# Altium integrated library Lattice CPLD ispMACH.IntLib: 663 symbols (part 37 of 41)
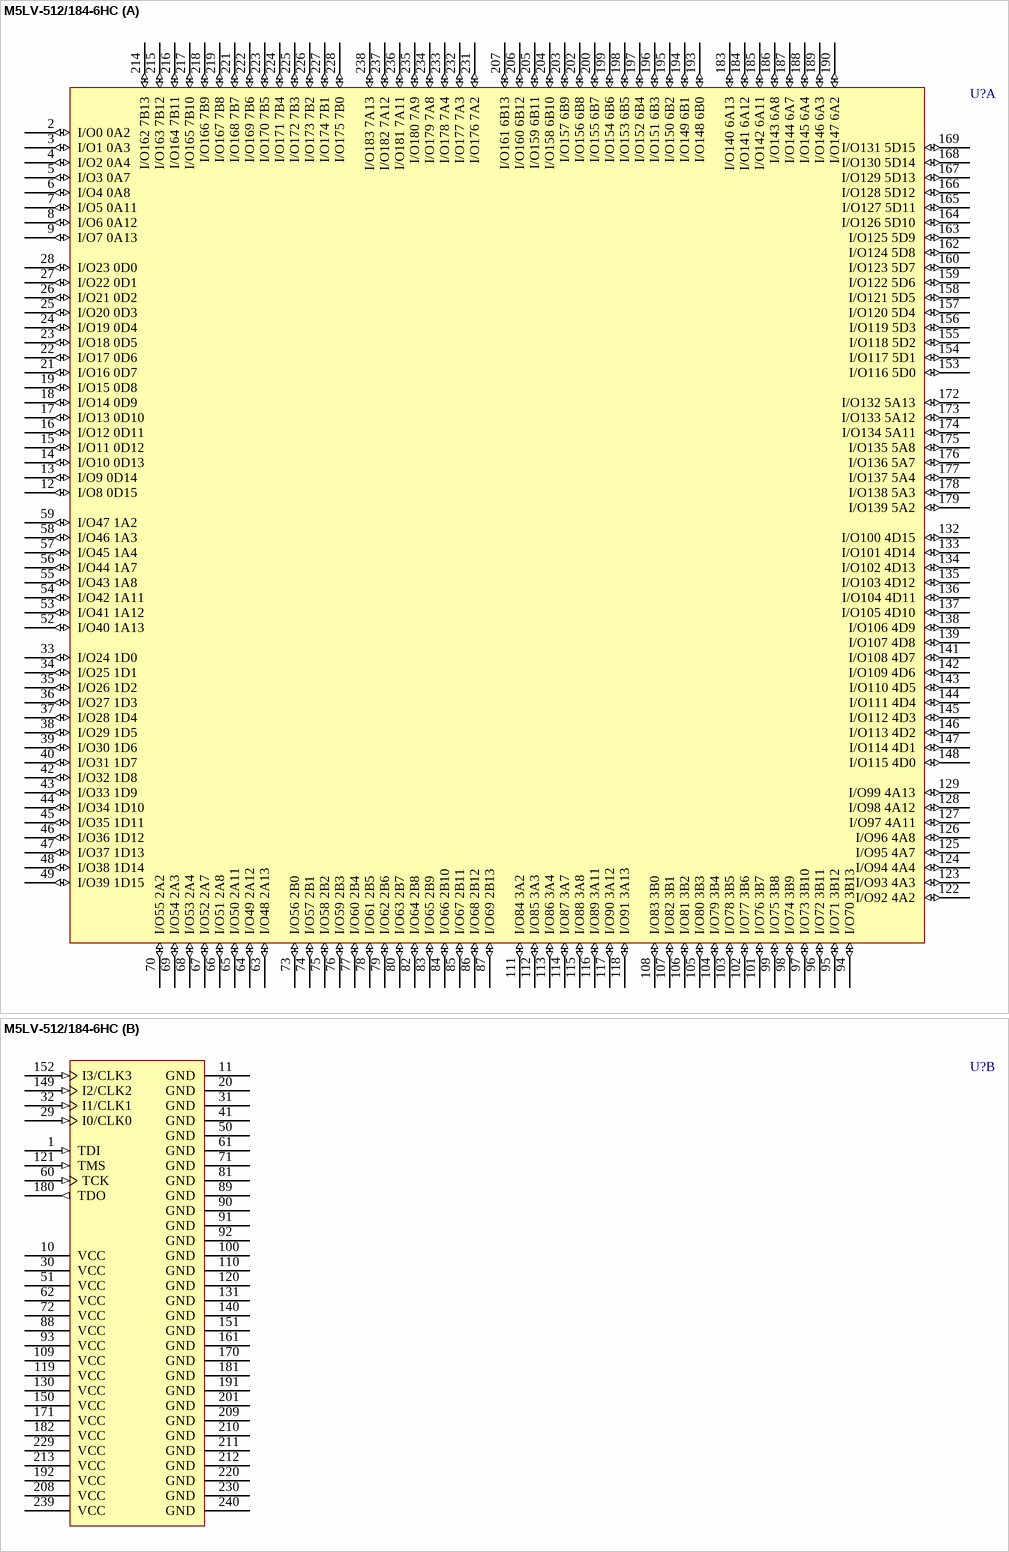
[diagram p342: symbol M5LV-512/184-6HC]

## M5LV-512/184-6HC
designator U?
High-Density and High-I/O Complex PLD
footprint PQFP240_N (Shrink QFP, 240-Leads, Body 32x32mm, Pitch 0.5mm, IPC Medium Density)
footprint PQFP240_L (Shrink QFP, 240-Leads, Body 32x32mm, Pitch 0.5mm, IPC High Density)
footprint PQFP240_M (Shrink QFP, 240-Leads, Body 32x32mm, Pitch 0.5mm, IPC Low Density)
3D model M5LV-PQFP240 (240-Pin Shrink Quad Flat Pack 0.5 mm Pitch)
part A pins: 2 I/O0 0A2 (io), 3 I/O1 0A3 (io), 4 I/O2 0A4 (io), 5 I/O3 0A7 (io), 6 I/O4 0A8 (io), 7 I/O5 0A11 (io), 8 I/O6 0A12 (io), 9 I/O7 0A13 (io), 12 I/O8 0D15 (io), 13 I/O9 0D14 (io), 14 I/O10 0D13 (io), 15 I/O11 0D12 (io), 16 I/O12 0D11 (io), 17 I/O13 0D10 (io), 18 I/O14 0D9 (io), 19 I/O15 0D8 (io), 21 I/O16 0D7 (io), 22 I/O17 0D6 (io), 23 I/O18 0D5 (io), 24 I/O19 0D4 (io), 25 I/O20 0D3 (io), 26 I/O21 0D2 (io), 27 I/O22 0D1 (io), 28 I/O23 0D0 (io), 33 I/O24 1D0 (io), 34 I/O25 1D1 (io), 35 I/O26 1D2 (io), 36 I/O27 1D3 (io), 37 I/O28 1D4 (io), 38 I/O29 1D5 (io), 39 I/O30 1D6 (io), 40 I/O31 1D7 (io), 42 I/O32 1D8 (io), 43 I/O33 1D9 (io), 44 I/O34 1D10 (io), 45 I/O35 1D11 (io), 46 I/O36 1D12 (io), 47 I/O37 1D13 (io), 48 I/O38 1D14 (io), 49 I/O39 1D15 (io), 52 I/O40 1A13 (io), 53 I/O41 1A12 (io), 54 I/O42 1A11 (io), 55 I/O43 1A8 (io), 56 I/O44 1A7 (io), 57 I/O45 1A4 (io), 58 I/O46 1A3 (io), 59 I/O47 1A2 (io), 63 I/O48 2A13 (io), 64 I/O49 2A12 (io), 65 I/O50 2A11 (io), 66 I/O51 2A8 (io), 67 I/O52 2A7 (io), 68 I/O53 2A4 (io), 69 I/O54 2A3 (io), 70 I/O55 2A2 (io), 73 I/O56 2B0 (io), 74 I/O57 2B1 (io), 75 I/O58 2B2 (io), 76 I/O59 2B3 (io), 77 I/O60 2B4 (io), 78 I/O61 2B5 (io), 79 I/O62 2B6 (io), 80 I/O63 2B7 (io), 82 I/O64 2B8 (io), 83 I/O65 2B9 (io), 84 I/O66 2B10 (io), 85 I/O67 2B11 (io), 86 I/O68 2B12 (io), 87 I/O69 2B13 (io), 94 I/O70 3B13 (io), 95 I/O71 3B12 (io), 96 I/O72 3B11 (io), 97 I/O73 3B10 (io), 98 I/O74 3B9 (io), 99 I/O75 3B8 (io), 101 I/O76 3B7 (io), 102 I/O77 3B6 (io), 103 I/O78 3B5 (io), 104 I/O79 3B4 (io), 105 I/O80 3B3 (io), 106 I/O81 3B2 (io), 107 I/O82 3B1 (io), 108 I/O83 3B0 (io), 111 I/O84 3A2 (io), 112 I/O85 3A3 (io), 113 I/O86 3A4 (io), 114 I/O87 3A7 (io), 115 I/O88 3A8 (io), 116 I/O89 3A11 (io), 117 I/O90 3A12 (io), 118 I/O91 3A13 (io), 122 I/O92 4A2 (io), 123 I/O93 4A3 (io), 124 I/O94 4A4 (io), 125 I/O95 4A7 (io), 126 I/O96 4A8 (io), 127 I/O97 4A11 (io), 128 I/O98 4A12 (io), 129 I/O99 4A13 (io), 132 I/O100 4D15 (io), 133 I/O101 4D14 (io), 134 I/O102 4D13 (io), 135 I/O103 4D12 (io), 136 I/O104 4D11 (io), 137 I/O105 4D10 (io), 138 I/O106 4D9 (io), 139 I/O107 4D8 (io), 141 I/O108 4D7 (io), 142 I/O109 4D6 (io), 143 I/O110 4D5 (io), 144 I/O111 4D4 (io), 145 I/O112 4D3 (io), 146 I/O113 4D2 (io), 147 I/O114 4D1 (io), 148 I/O115 4D0 (io), 153 I/O116 5D0 (io), 154 I/O117 5D1 (io), 155 I/O118 5D2 (io), 156 I/O119 5D3 (io), 157 I/O120 5D4 (io), 158 I/O121 5D5 (io), 159 I/O122 5D6 (io), 160 I/O123 5D7 (io), 162 I/O124 5D8 (io), 163 I/O125 5D9 (io), 164 I/O126 5D10 (io), 165 I/O127 5D11 (io), 166 I/O128 5D12 (io), 167 I/O129 5D13 (io), 168 I/O130 5D14 (io), 169 I/O131 5D15 (io), 172 I/O132 5A13 (io), 173 I/O133 5A12 (io), 174 I/O134 5A11 (io), 175 I/O135 5A8 (io), 176 I/O136 5A7 (io), 177 I/O137 5A4 (io), 178 I/O138 5A3 (io), 179 I/O139 5A2 (io), 183 I/O140 6A13 (io), 184 I/O141 6A12 (io), 185 I/O142 6A11 (io), 186 I/O143 6A8 (io), 187 I/O144 6A7 (io), 188 I/O145 6A4 (io), 189 I/O146 6A3 (io), 190 I/O147 6A2 (io), 193 I/O148 6B0 (io), 194 I/O149 6B1 (io), 195 I/O150 6B2 (io), 196 I/O151 6B3 (io), 197 I/O152 6B4 (io), 198 I/O153 6B5 (io), 199 I/O154 6B6 (io), 200 I/O155 6B7 (io), 202 I/O156 6B8 (io), 203 I/O157 6B9 (io), 204 I/O158 6B10 (io), 205 I/O159 6B11 (io), 206 I/O160 6B12 (io), 207 I/O161 6B13 (io), 214 I/O162 7B13 (io), 215 I/O163 7B12 (io), 216 I/O164 7B11 (io), 217 I/O165 7B10 (io), 218 I/O166 7B9 (io), 219 I/O167 7B8 (io), 221 I/O168 7B7 (io), 222 I/O169 7B6 (io), 223 I/O170 7B5 (io), 224 I/O171 7B4 (io), 225 I/O172 7B3 (io), 226 I/O173 7B2 (io), 227 I/O174 7B1 (io), 228 I/O175 7B0 (io), 231 I/O176 7A2 (io), 232 I/O177 7A3 (io), 233 I/O178 7A4 (io), 234 I/O179 7A8 (io), 235 I/O180 7A9 (io), 236 I/O181 7A11 (io), 237 I/O182 7A12 (io), 238 I/O183 7A13 (io)
part B pins: 1 TDI (in), 10 VCC (power), 11 GND (power), 20 GND (power), 29 I0/CLK0 (in), 30 VCC (power), 31 GND (power), 32 I1/CLK1 (in), 41 GND (power), 50 GND (power), 51 VCC (power), 60 TCK (in), 61 GND (power), 62 VCC (power), 71 GND (power), 72 VCC (power), 81 GND (power), 88 VCC (power), 89 GND (power), 90 GND (power), 91 GND (power), 92 GND (power), 93 VCC (power), 100 GND (power), 109 VCC (power), 110 GND (power), 119 VCC (power), 120 GND (power), 121 TMS (in), 130 VCC (power), 131 GND (power), 140 GND (power), 149 I2/CLK2 (in), 150 VCC (power), 151 GND (power), 152 I3/CLK3 (in), 161 GND (power), 170 GND (power), 171 VCC (power), 180 TDO (out), 181 GND (power), 182 VCC (power), 191 GND (power), 192 VCC (power), 201 GND (power), 208 VCC (power), 209 GND (power), 210 GND (power), 211 GND (power), 212 GND (power), 213 VCC (power), 220 GND (power), 229 VCC (power), 230 GND (power), 239 VCC (power), 240 GND (power)

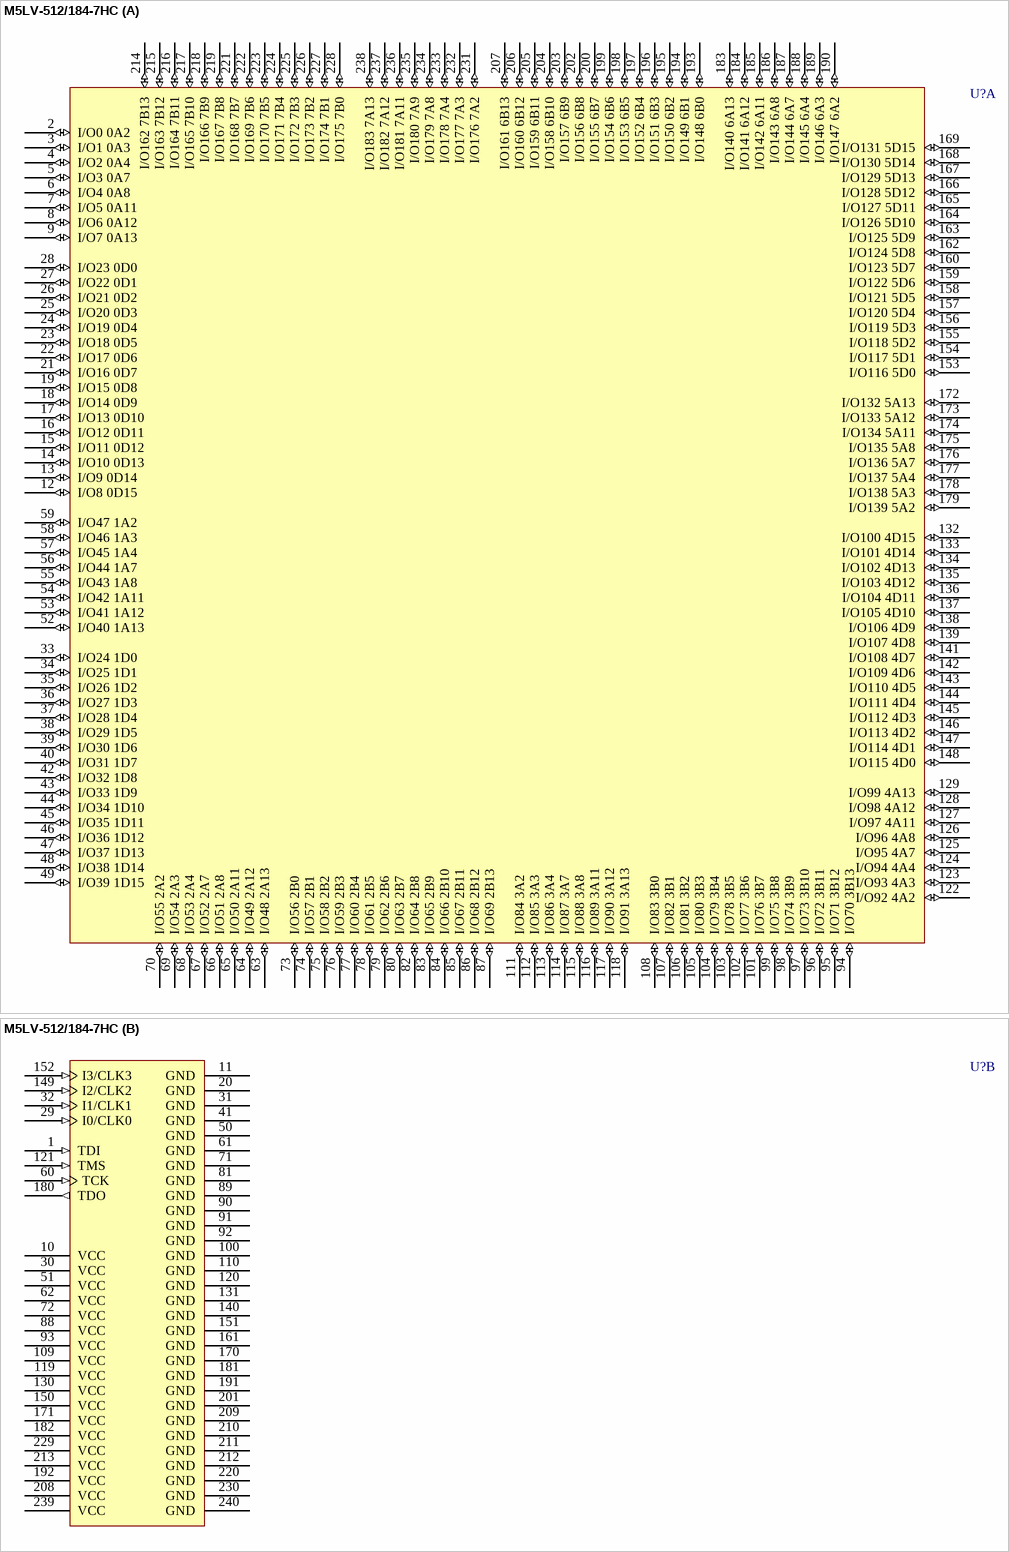
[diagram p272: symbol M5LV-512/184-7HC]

## M5LV-512/184-7HC
designator U?
High-Density and High-I/O Complex PLD
footprint PQFP240_N (Shrink QFP, 240-Leads, Body 32x32mm, Pitch 0.5mm, IPC Medium Density)
footprint PQFP240_L (Shrink QFP, 240-Leads, Body 32x32mm, Pitch 0.5mm, IPC High Density)
footprint PQFP240_M (Shrink QFP, 240-Leads, Body 32x32mm, Pitch 0.5mm, IPC Low Density)
3D model M5LV-PQFP240 (240-Pin Shrink Quad Flat Pack 0.5 mm Pitch)
part A pins: 2 I/O0 0A2 (io), 3 I/O1 0A3 (io), 4 I/O2 0A4 (io), 5 I/O3 0A7 (io), 6 I/O4 0A8 (io), 7 I/O5 0A11 (io), 8 I/O6 0A12 (io), 9 I/O7 0A13 (io), 12 I/O8 0D15 (io), 13 I/O9 0D14 (io), 14 I/O10 0D13 (io), 15 I/O11 0D12 (io), 16 I/O12 0D11 (io), 17 I/O13 0D10 (io), 18 I/O14 0D9 (io), 19 I/O15 0D8 (io), 21 I/O16 0D7 (io), 22 I/O17 0D6 (io), 23 I/O18 0D5 (io), 24 I/O19 0D4 (io), 25 I/O20 0D3 (io), 26 I/O21 0D2 (io), 27 I/O22 0D1 (io), 28 I/O23 0D0 (io), 33 I/O24 1D0 (io), 34 I/O25 1D1 (io), 35 I/O26 1D2 (io), 36 I/O27 1D3 (io), 37 I/O28 1D4 (io), 38 I/O29 1D5 (io), 39 I/O30 1D6 (io), 40 I/O31 1D7 (io), 42 I/O32 1D8 (io), 43 I/O33 1D9 (io), 44 I/O34 1D10 (io), 45 I/O35 1D11 (io), 46 I/O36 1D12 (io), 47 I/O37 1D13 (io), 48 I/O38 1D14 (io), 49 I/O39 1D15 (io), 52 I/O40 1A13 (io), 53 I/O41 1A12 (io), 54 I/O42 1A11 (io), 55 I/O43 1A8 (io), 56 I/O44 1A7 (io), 57 I/O45 1A4 (io), 58 I/O46 1A3 (io), 59 I/O47 1A2 (io), 63 I/O48 2A13 (io), 64 I/O49 2A12 (io), 65 I/O50 2A11 (io), 66 I/O51 2A8 (io), 67 I/O52 2A7 (io), 68 I/O53 2A4 (io), 69 I/O54 2A3 (io), 70 I/O55 2A2 (io), 73 I/O56 2B0 (io), 74 I/O57 2B1 (io), 75 I/O58 2B2 (io), 76 I/O59 2B3 (io), 77 I/O60 2B4 (io), 78 I/O61 2B5 (io), 79 I/O62 2B6 (io), 80 I/O63 2B7 (io), 82 I/O64 2B8 (io), 83 I/O65 2B9 (io), 84 I/O66 2B10 (io), 85 I/O67 2B11 (io), 86 I/O68 2B12 (io), 87 I/O69 2B13 (io), 94 I/O70 3B13 (io), 95 I/O71 3B12 (io), 96 I/O72 3B11 (io), 97 I/O73 3B10 (io), 98 I/O74 3B9 (io), 99 I/O75 3B8 (io), 101 I/O76 3B7 (io), 102 I/O77 3B6 (io), 103 I/O78 3B5 (io), 104 I/O79 3B4 (io), 105 I/O80 3B3 (io), 106 I/O81 3B2 (io), 107 I/O82 3B1 (io), 108 I/O83 3B0 (io), 111 I/O84 3A2 (io), 112 I/O85 3A3 (io), 113 I/O86 3A4 (io), 114 I/O87 3A7 (io), 115 I/O88 3A8 (io), 116 I/O89 3A11 (io), 117 I/O90 3A12 (io), 118 I/O91 3A13 (io), 122 I/O92 4A2 (io), 123 I/O93 4A3 (io), 124 I/O94 4A4 (io), 125 I/O95 4A7 (io), 126 I/O96 4A8 (io), 127 I/O97 4A11 (io), 128 I/O98 4A12 (io), 129 I/O99 4A13 (io), 132 I/O100 4D15 (io), 133 I/O101 4D14 (io), 134 I/O102 4D13 (io), 135 I/O103 4D12 (io), 136 I/O104 4D11 (io), 137 I/O105 4D10 (io), 138 I/O106 4D9 (io), 139 I/O107 4D8 (io), 141 I/O108 4D7 (io), 142 I/O109 4D6 (io), 143 I/O110 4D5 (io), 144 I/O111 4D4 (io), 145 I/O112 4D3 (io), 146 I/O113 4D2 (io), 147 I/O114 4D1 (io), 148 I/O115 4D0 (io), 153 I/O116 5D0 (io), 154 I/O117 5D1 (io), 155 I/O118 5D2 (io), 156 I/O119 5D3 (io), 157 I/O120 5D4 (io), 158 I/O121 5D5 (io), 159 I/O122 5D6 (io), 160 I/O123 5D7 (io), 162 I/O124 5D8 (io), 163 I/O125 5D9 (io), 164 I/O126 5D10 (io), 165 I/O127 5D11 (io), 166 I/O128 5D12 (io), 167 I/O129 5D13 (io), 168 I/O130 5D14 (io), 169 I/O131 5D15 (io), 172 I/O132 5A13 (io), 173 I/O133 5A12 (io), 174 I/O134 5A11 (io), 175 I/O135 5A8 (io), 176 I/O136 5A7 (io), 177 I/O137 5A4 (io), 178 I/O138 5A3 (io), 179 I/O139 5A2 (io), 183 I/O140 6A13 (io), 184 I/O141 6A12 (io), 185 I/O142 6A11 (io), 186 I/O143 6A8 (io), 187 I/O144 6A7 (io), 188 I/O145 6A4 (io), 189 I/O146 6A3 (io), 190 I/O147 6A2 (io), 193 I/O148 6B0 (io), 194 I/O149 6B1 (io), 195 I/O150 6B2 (io), 196 I/O151 6B3 (io), 197 I/O152 6B4 (io), 198 I/O153 6B5 (io), 199 I/O154 6B6 (io), 200 I/O155 6B7 (io), 202 I/O156 6B8 (io), 203 I/O157 6B9 (io), 204 I/O158 6B10 (io), 205 I/O159 6B11 (io), 206 I/O160 6B12 (io), 207 I/O161 6B13 (io), 214 I/O162 7B13 (io), 215 I/O163 7B12 (io), 216 I/O164 7B11 (io), 217 I/O165 7B10 (io), 218 I/O166 7B9 (io), 219 I/O167 7B8 (io), 221 I/O168 7B7 (io), 222 I/O169 7B6 (io), 223 I/O170 7B5 (io), 224 I/O171 7B4 (io), 225 I/O172 7B3 (io), 226 I/O173 7B2 (io), 227 I/O174 7B1 (io), 228 I/O175 7B0 (io), 231 I/O176 7A2 (io), 232 I/O177 7A3 (io), 233 I/O178 7A4 (io), 234 I/O179 7A8 (io), 235 I/O180 7A9 (io), 236 I/O181 7A11 (io), 237 I/O182 7A12 (io), 238 I/O183 7A13 (io)
part B pins: 1 TDI (in), 10 VCC (power), 11 GND (power), 20 GND (power), 29 I0/CLK0 (in), 30 VCC (power), 31 GND (power), 32 I1/CLK1 (in), 41 GND (power), 50 GND (power), 51 VCC (power), 60 TCK (in), 61 GND (power), 62 VCC (power), 71 GND (power), 72 VCC (power), 81 GND (power), 88 VCC (power), 89 GND (power), 90 GND (power), 91 GND (power), 92 GND (power), 93 VCC (power), 100 GND (power), 109 VCC (power), 110 GND (power), 119 VCC (power), 120 GND (power), 121 TMS (in), 130 VCC (power), 131 GND (power), 140 GND (power), 149 I2/CLK2 (in), 150 VCC (power), 151 GND (power), 152 I3/CLK3 (in), 161 GND (power), 170 GND (power), 171 VCC (power), 180 TDO (out), 181 GND (power), 182 VCC (power), 191 GND (power), 192 VCC (power), 201 GND (power), 208 VCC (power), 209 GND (power), 210 GND (power), 211 GND (power), 212 GND (power), 213 VCC (power), 220 GND (power), 229 VCC (power), 230 GND (power), 239 VCC (power), 240 GND (power)

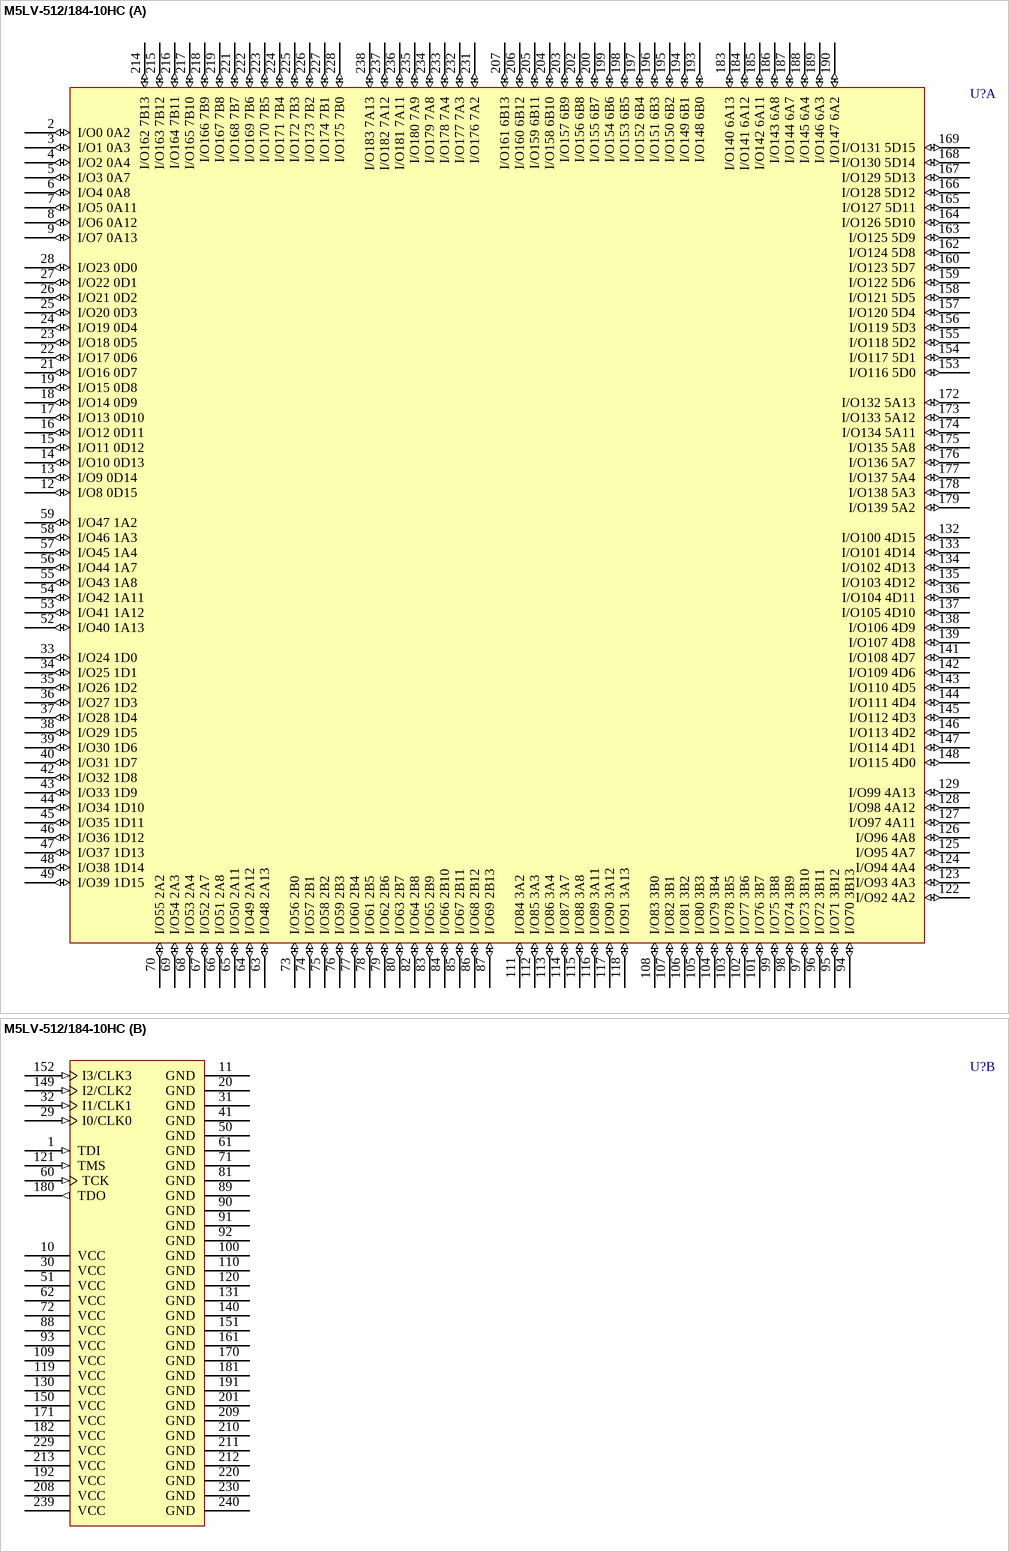
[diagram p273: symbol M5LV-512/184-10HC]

## M5LV-512/184-10HC
designator U?
High-Density and High-I/O Complex PLD
footprint PQFP240_N (Shrink QFP, 240-Leads, Body 32x32mm, Pitch 0.5mm, IPC Medium Density)
footprint PQFP240_L (Shrink QFP, 240-Leads, Body 32x32mm, Pitch 0.5mm, IPC High Density)
footprint PQFP240_M (Shrink QFP, 240-Leads, Body 32x32mm, Pitch 0.5mm, IPC Low Density)
3D model M5LV-PQFP240 (240-Pin Shrink Quad Flat Pack 0.5 mm Pitch)
part A pins: 2 I/O0 0A2 (io), 3 I/O1 0A3 (io), 4 I/O2 0A4 (io), 5 I/O3 0A7 (io), 6 I/O4 0A8 (io), 7 I/O5 0A11 (io), 8 I/O6 0A12 (io), 9 I/O7 0A13 (io), 12 I/O8 0D15 (io), 13 I/O9 0D14 (io), 14 I/O10 0D13 (io), 15 I/O11 0D12 (io), 16 I/O12 0D11 (io), 17 I/O13 0D10 (io), 18 I/O14 0D9 (io), 19 I/O15 0D8 (io), 21 I/O16 0D7 (io), 22 I/O17 0D6 (io), 23 I/O18 0D5 (io), 24 I/O19 0D4 (io), 25 I/O20 0D3 (io), 26 I/O21 0D2 (io), 27 I/O22 0D1 (io), 28 I/O23 0D0 (io), 33 I/O24 1D0 (io), 34 I/O25 1D1 (io), 35 I/O26 1D2 (io), 36 I/O27 1D3 (io), 37 I/O28 1D4 (io), 38 I/O29 1D5 (io), 39 I/O30 1D6 (io), 40 I/O31 1D7 (io), 42 I/O32 1D8 (io), 43 I/O33 1D9 (io), 44 I/O34 1D10 (io), 45 I/O35 1D11 (io), 46 I/O36 1D12 (io), 47 I/O37 1D13 (io), 48 I/O38 1D14 (io), 49 I/O39 1D15 (io), 52 I/O40 1A13 (io), 53 I/O41 1A12 (io), 54 I/O42 1A11 (io), 55 I/O43 1A8 (io), 56 I/O44 1A7 (io), 57 I/O45 1A4 (io), 58 I/O46 1A3 (io), 59 I/O47 1A2 (io), 63 I/O48 2A13 (io), 64 I/O49 2A12 (io), 65 I/O50 2A11 (io), 66 I/O51 2A8 (io), 67 I/O52 2A7 (io), 68 I/O53 2A4 (io), 69 I/O54 2A3 (io), 70 I/O55 2A2 (io), 73 I/O56 2B0 (io), 74 I/O57 2B1 (io), 75 I/O58 2B2 (io), 76 I/O59 2B3 (io), 77 I/O60 2B4 (io), 78 I/O61 2B5 (io), 79 I/O62 2B6 (io), 80 I/O63 2B7 (io), 82 I/O64 2B8 (io), 83 I/O65 2B9 (io), 84 I/O66 2B10 (io), 85 I/O67 2B11 (io), 86 I/O68 2B12 (io), 87 I/O69 2B13 (io), 94 I/O70 3B13 (io), 95 I/O71 3B12 (io), 96 I/O72 3B11 (io), 97 I/O73 3B10 (io), 98 I/O74 3B9 (io), 99 I/O75 3B8 (io), 101 I/O76 3B7 (io), 102 I/O77 3B6 (io), 103 I/O78 3B5 (io), 104 I/O79 3B4 (io), 105 I/O80 3B3 (io), 106 I/O81 3B2 (io), 107 I/O82 3B1 (io), 108 I/O83 3B0 (io), 111 I/O84 3A2 (io), 112 I/O85 3A3 (io), 113 I/O86 3A4 (io), 114 I/O87 3A7 (io), 115 I/O88 3A8 (io), 116 I/O89 3A11 (io), 117 I/O90 3A12 (io), 118 I/O91 3A13 (io), 122 I/O92 4A2 (io), 123 I/O93 4A3 (io), 124 I/O94 4A4 (io), 125 I/O95 4A7 (io), 126 I/O96 4A8 (io), 127 I/O97 4A11 (io), 128 I/O98 4A12 (io), 129 I/O99 4A13 (io), 132 I/O100 4D15 (io), 133 I/O101 4D14 (io), 134 I/O102 4D13 (io), 135 I/O103 4D12 (io), 136 I/O104 4D11 (io), 137 I/O105 4D10 (io), 138 I/O106 4D9 (io), 139 I/O107 4D8 (io), 141 I/O108 4D7 (io), 142 I/O109 4D6 (io), 143 I/O110 4D5 (io), 144 I/O111 4D4 (io), 145 I/O112 4D3 (io), 146 I/O113 4D2 (io), 147 I/O114 4D1 (io), 148 I/O115 4D0 (io), 153 I/O116 5D0 (io), 154 I/O117 5D1 (io), 155 I/O118 5D2 (io), 156 I/O119 5D3 (io), 157 I/O120 5D4 (io), 158 I/O121 5D5 (io), 159 I/O122 5D6 (io), 160 I/O123 5D7 (io), 162 I/O124 5D8 (io), 163 I/O125 5D9 (io), 164 I/O126 5D10 (io), 165 I/O127 5D11 (io), 166 I/O128 5D12 (io), 167 I/O129 5D13 (io), 168 I/O130 5D14 (io), 169 I/O131 5D15 (io), 172 I/O132 5A13 (io), 173 I/O133 5A12 (io), 174 I/O134 5A11 (io), 175 I/O135 5A8 (io), 176 I/O136 5A7 (io), 177 I/O137 5A4 (io), 178 I/O138 5A3 (io), 179 I/O139 5A2 (io), 183 I/O140 6A13 (io), 184 I/O141 6A12 (io), 185 I/O142 6A11 (io), 186 I/O143 6A8 (io), 187 I/O144 6A7 (io), 188 I/O145 6A4 (io), 189 I/O146 6A3 (io), 190 I/O147 6A2 (io), 193 I/O148 6B0 (io), 194 I/O149 6B1 (io), 195 I/O150 6B2 (io), 196 I/O151 6B3 (io), 197 I/O152 6B4 (io), 198 I/O153 6B5 (io), 199 I/O154 6B6 (io), 200 I/O155 6B7 (io), 202 I/O156 6B8 (io), 203 I/O157 6B9 (io), 204 I/O158 6B10 (io), 205 I/O159 6B11 (io), 206 I/O160 6B12 (io), 207 I/O161 6B13 (io), 214 I/O162 7B13 (io), 215 I/O163 7B12 (io), 216 I/O164 7B11 (io), 217 I/O165 7B10 (io), 218 I/O166 7B9 (io), 219 I/O167 7B8 (io), 221 I/O168 7B7 (io), 222 I/O169 7B6 (io), 223 I/O170 7B5 (io), 224 I/O171 7B4 (io), 225 I/O172 7B3 (io), 226 I/O173 7B2 (io), 227 I/O174 7B1 (io), 228 I/O175 7B0 (io), 231 I/O176 7A2 (io), 232 I/O177 7A3 (io), 233 I/O178 7A4 (io), 234 I/O179 7A8 (io), 235 I/O180 7A9 (io), 236 I/O181 7A11 (io), 237 I/O182 7A12 (io), 238 I/O183 7A13 (io)
part B pins: 1 TDI (in), 10 VCC (power), 11 GND (power), 20 GND (power), 29 I0/CLK0 (in), 30 VCC (power), 31 GND (power), 32 I1/CLK1 (in), 41 GND (power), 50 GND (power), 51 VCC (power), 60 TCK (in), 61 GND (power), 62 VCC (power), 71 GND (power), 72 VCC (power), 81 GND (power), 88 VCC (power), 89 GND (power), 90 GND (power), 91 GND (power), 92 GND (power), 93 VCC (power), 100 GND (power), 109 VCC (power), 110 GND (power), 119 VCC (power), 120 GND (power), 121 TMS (in), 130 VCC (power), 131 GND (power), 140 GND (power), 149 I2/CLK2 (in), 150 VCC (power), 151 GND (power), 152 I3/CLK3 (in), 161 GND (power), 170 GND (power), 171 VCC (power), 180 TDO (out), 181 GND (power), 182 VCC (power), 191 GND (power), 192 VCC (power), 201 GND (power), 208 VCC (power), 209 GND (power), 210 GND (power), 211 GND (power), 212 GND (power), 213 VCC (power), 220 GND (power), 229 VCC (power), 230 GND (power), 239 VCC (power), 240 GND (power)

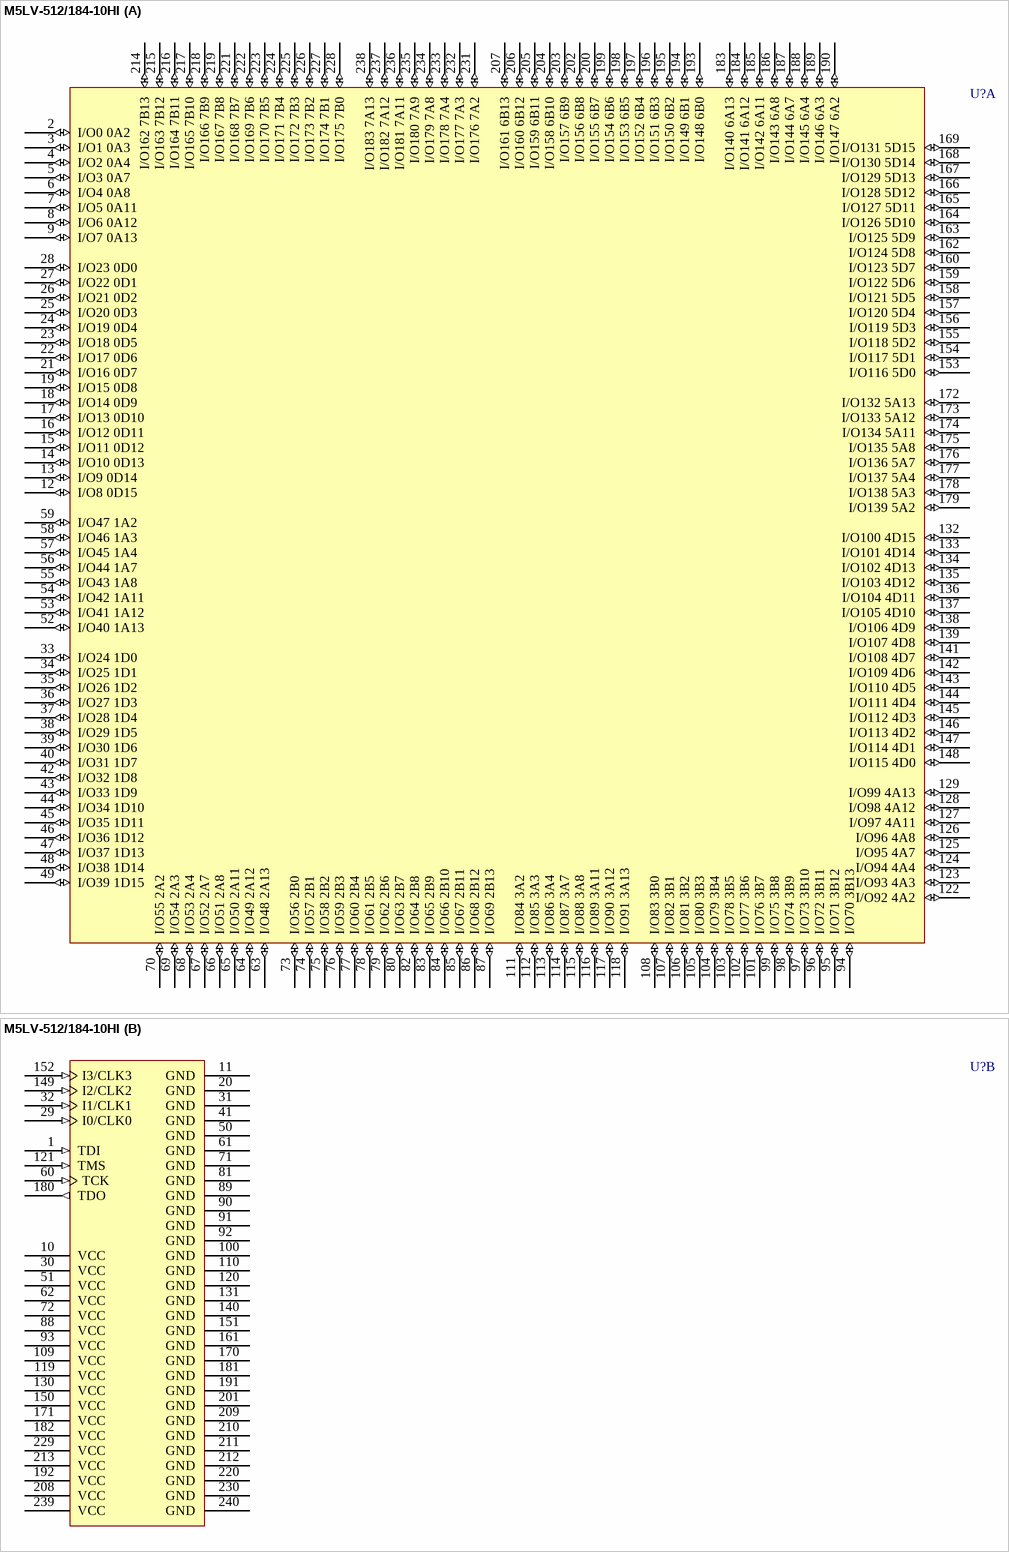
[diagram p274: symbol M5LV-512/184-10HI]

## M5LV-512/184-10HI
designator U?
High-Density and High-I/O Complex PLD
footprint PQFP240_N (Shrink QFP, 240-Leads, Body 32x32mm, Pitch 0.5mm, IPC Medium Density)
footprint PQFP240_L (Shrink QFP, 240-Leads, Body 32x32mm, Pitch 0.5mm, IPC High Density)
footprint PQFP240_M (Shrink QFP, 240-Leads, Body 32x32mm, Pitch 0.5mm, IPC Low Density)
3D model M5LV-PQFP240 (240-Pin Shrink Quad Flat Pack 0.5 mm Pitch)
part A pins: 2 I/O0 0A2 (io), 3 I/O1 0A3 (io), 4 I/O2 0A4 (io), 5 I/O3 0A7 (io), 6 I/O4 0A8 (io), 7 I/O5 0A11 (io), 8 I/O6 0A12 (io), 9 I/O7 0A13 (io), 12 I/O8 0D15 (io), 13 I/O9 0D14 (io), 14 I/O10 0D13 (io), 15 I/O11 0D12 (io), 16 I/O12 0D11 (io), 17 I/O13 0D10 (io), 18 I/O14 0D9 (io), 19 I/O15 0D8 (io), 21 I/O16 0D7 (io), 22 I/O17 0D6 (io), 23 I/O18 0D5 (io), 24 I/O19 0D4 (io), 25 I/O20 0D3 (io), 26 I/O21 0D2 (io), 27 I/O22 0D1 (io), 28 I/O23 0D0 (io), 33 I/O24 1D0 (io), 34 I/O25 1D1 (io), 35 I/O26 1D2 (io), 36 I/O27 1D3 (io), 37 I/O28 1D4 (io), 38 I/O29 1D5 (io), 39 I/O30 1D6 (io), 40 I/O31 1D7 (io), 42 I/O32 1D8 (io), 43 I/O33 1D9 (io), 44 I/O34 1D10 (io), 45 I/O35 1D11 (io), 46 I/O36 1D12 (io), 47 I/O37 1D13 (io), 48 I/O38 1D14 (io), 49 I/O39 1D15 (io), 52 I/O40 1A13 (io), 53 I/O41 1A12 (io), 54 I/O42 1A11 (io), 55 I/O43 1A8 (io), 56 I/O44 1A7 (io), 57 I/O45 1A4 (io), 58 I/O46 1A3 (io), 59 I/O47 1A2 (io), 63 I/O48 2A13 (io), 64 I/O49 2A12 (io), 65 I/O50 2A11 (io), 66 I/O51 2A8 (io), 67 I/O52 2A7 (io), 68 I/O53 2A4 (io), 69 I/O54 2A3 (io), 70 I/O55 2A2 (io), 73 I/O56 2B0 (io), 74 I/O57 2B1 (io), 75 I/O58 2B2 (io), 76 I/O59 2B3 (io), 77 I/O60 2B4 (io), 78 I/O61 2B5 (io), 79 I/O62 2B6 (io), 80 I/O63 2B7 (io), 82 I/O64 2B8 (io), 83 I/O65 2B9 (io), 84 I/O66 2B10 (io), 85 I/O67 2B11 (io), 86 I/O68 2B12 (io), 87 I/O69 2B13 (io), 94 I/O70 3B13 (io), 95 I/O71 3B12 (io), 96 I/O72 3B11 (io), 97 I/O73 3B10 (io), 98 I/O74 3B9 (io), 99 I/O75 3B8 (io), 101 I/O76 3B7 (io), 102 I/O77 3B6 (io), 103 I/O78 3B5 (io), 104 I/O79 3B4 (io), 105 I/O80 3B3 (io), 106 I/O81 3B2 (io), 107 I/O82 3B1 (io), 108 I/O83 3B0 (io), 111 I/O84 3A2 (io), 112 I/O85 3A3 (io), 113 I/O86 3A4 (io), 114 I/O87 3A7 (io), 115 I/O88 3A8 (io), 116 I/O89 3A11 (io), 117 I/O90 3A12 (io), 118 I/O91 3A13 (io), 122 I/O92 4A2 (io), 123 I/O93 4A3 (io), 124 I/O94 4A4 (io), 125 I/O95 4A7 (io), 126 I/O96 4A8 (io), 127 I/O97 4A11 (io), 128 I/O98 4A12 (io), 129 I/O99 4A13 (io), 132 I/O100 4D15 (io), 133 I/O101 4D14 (io), 134 I/O102 4D13 (io), 135 I/O103 4D12 (io), 136 I/O104 4D11 (io), 137 I/O105 4D10 (io), 138 I/O106 4D9 (io), 139 I/O107 4D8 (io), 141 I/O108 4D7 (io), 142 I/O109 4D6 (io), 143 I/O110 4D5 (io), 144 I/O111 4D4 (io), 145 I/O112 4D3 (io), 146 I/O113 4D2 (io), 147 I/O114 4D1 (io), 148 I/O115 4D0 (io), 153 I/O116 5D0 (io), 154 I/O117 5D1 (io), 155 I/O118 5D2 (io), 156 I/O119 5D3 (io), 157 I/O120 5D4 (io), 158 I/O121 5D5 (io), 159 I/O122 5D6 (io), 160 I/O123 5D7 (io), 162 I/O124 5D8 (io), 163 I/O125 5D9 (io), 164 I/O126 5D10 (io), 165 I/O127 5D11 (io), 166 I/O128 5D12 (io), 167 I/O129 5D13 (io), 168 I/O130 5D14 (io), 169 I/O131 5D15 (io), 172 I/O132 5A13 (io), 173 I/O133 5A12 (io), 174 I/O134 5A11 (io), 175 I/O135 5A8 (io), 176 I/O136 5A7 (io), 177 I/O137 5A4 (io), 178 I/O138 5A3 (io), 179 I/O139 5A2 (io), 183 I/O140 6A13 (io), 184 I/O141 6A12 (io), 185 I/O142 6A11 (io), 186 I/O143 6A8 (io), 187 I/O144 6A7 (io), 188 I/O145 6A4 (io), 189 I/O146 6A3 (io), 190 I/O147 6A2 (io), 193 I/O148 6B0 (io), 194 I/O149 6B1 (io), 195 I/O150 6B2 (io), 196 I/O151 6B3 (io), 197 I/O152 6B4 (io), 198 I/O153 6B5 (io), 199 I/O154 6B6 (io), 200 I/O155 6B7 (io), 202 I/O156 6B8 (io), 203 I/O157 6B9 (io), 204 I/O158 6B10 (io), 205 I/O159 6B11 (io), 206 I/O160 6B12 (io), 207 I/O161 6B13 (io), 214 I/O162 7B13 (io), 215 I/O163 7B12 (io), 216 I/O164 7B11 (io), 217 I/O165 7B10 (io), 218 I/O166 7B9 (io), 219 I/O167 7B8 (io), 221 I/O168 7B7 (io), 222 I/O169 7B6 (io), 223 I/O170 7B5 (io), 224 I/O171 7B4 (io), 225 I/O172 7B3 (io), 226 I/O173 7B2 (io), 227 I/O174 7B1 (io), 228 I/O175 7B0 (io), 231 I/O176 7A2 (io), 232 I/O177 7A3 (io), 233 I/O178 7A4 (io), 234 I/O179 7A8 (io), 235 I/O180 7A9 (io), 236 I/O181 7A11 (io), 237 I/O182 7A12 (io), 238 I/O183 7A13 (io)
part B pins: 1 TDI (in), 10 VCC (power), 11 GND (power), 20 GND (power), 29 I0/CLK0 (in), 30 VCC (power), 31 GND (power), 32 I1/CLK1 (in), 41 GND (power), 50 GND (power), 51 VCC (power), 60 TCK (in), 61 GND (power), 62 VCC (power), 71 GND (power), 72 VCC (power), 81 GND (power), 88 VCC (power), 89 GND (power), 90 GND (power), 91 GND (power), 92 GND (power), 93 VCC (power), 100 GND (power), 109 VCC (power), 110 GND (power), 119 VCC (power), 120 GND (power), 121 TMS (in), 130 VCC (power), 131 GND (power), 140 GND (power), 149 I2/CLK2 (in), 150 VCC (power), 151 GND (power), 152 I3/CLK3 (in), 161 GND (power), 170 GND (power), 171 VCC (power), 180 TDO (out), 181 GND (power), 182 VCC (power), 191 GND (power), 192 VCC (power), 201 GND (power), 208 VCC (power), 209 GND (power), 210 GND (power), 211 GND (power), 212 GND (power), 213 VCC (power), 220 GND (power), 229 VCC (power), 230 GND (power), 239 VCC (power), 240 GND (power)

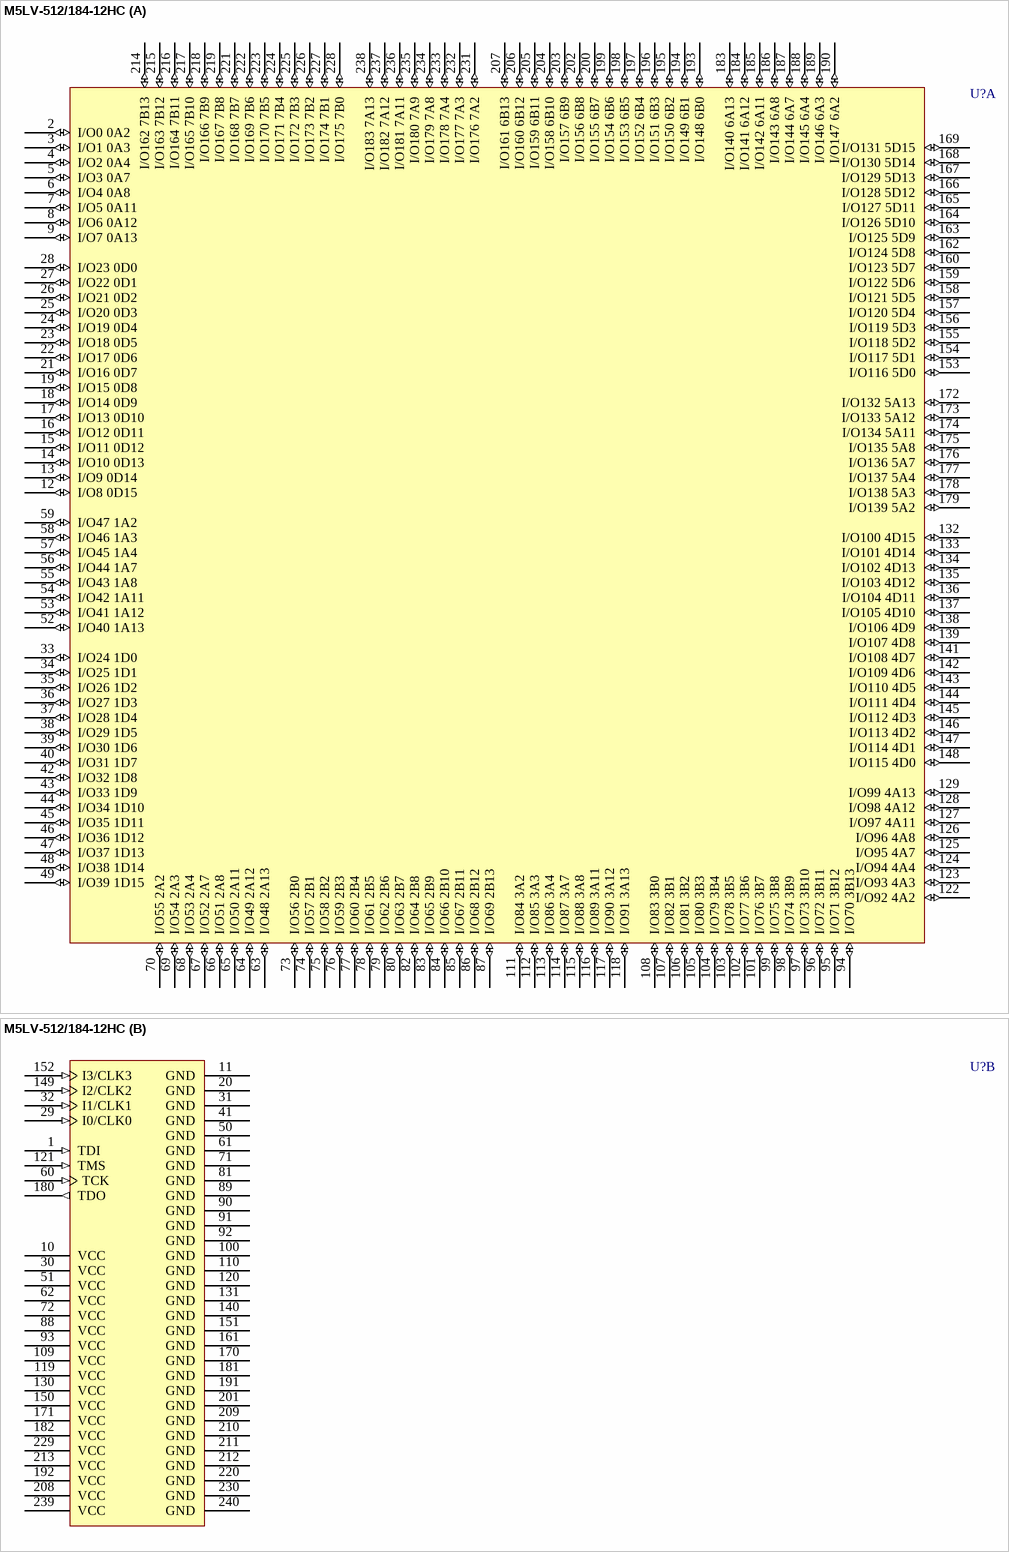
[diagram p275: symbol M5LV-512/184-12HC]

## M5LV-512/184-12HC
designator U?
High-Density and High-I/O Complex PLD
footprint PQFP240_N (Shrink QFP, 240-Leads, Body 32x32mm, Pitch 0.5mm, IPC Medium Density)
footprint PQFP240_L (Shrink QFP, 240-Leads, Body 32x32mm, Pitch 0.5mm, IPC High Density)
footprint PQFP240_M (Shrink QFP, 240-Leads, Body 32x32mm, Pitch 0.5mm, IPC Low Density)
3D model M5LV-PQFP240 (240-Pin Shrink Quad Flat Pack 0.5 mm Pitch)
part A pins: 2 I/O0 0A2 (io), 3 I/O1 0A3 (io), 4 I/O2 0A4 (io), 5 I/O3 0A7 (io), 6 I/O4 0A8 (io), 7 I/O5 0A11 (io), 8 I/O6 0A12 (io), 9 I/O7 0A13 (io), 12 I/O8 0D15 (io), 13 I/O9 0D14 (io), 14 I/O10 0D13 (io), 15 I/O11 0D12 (io), 16 I/O12 0D11 (io), 17 I/O13 0D10 (io), 18 I/O14 0D9 (io), 19 I/O15 0D8 (io), 21 I/O16 0D7 (io), 22 I/O17 0D6 (io), 23 I/O18 0D5 (io), 24 I/O19 0D4 (io), 25 I/O20 0D3 (io), 26 I/O21 0D2 (io), 27 I/O22 0D1 (io), 28 I/O23 0D0 (io), 33 I/O24 1D0 (io), 34 I/O25 1D1 (io), 35 I/O26 1D2 (io), 36 I/O27 1D3 (io), 37 I/O28 1D4 (io), 38 I/O29 1D5 (io), 39 I/O30 1D6 (io), 40 I/O31 1D7 (io), 42 I/O32 1D8 (io), 43 I/O33 1D9 (io), 44 I/O34 1D10 (io), 45 I/O35 1D11 (io), 46 I/O36 1D12 (io), 47 I/O37 1D13 (io), 48 I/O38 1D14 (io), 49 I/O39 1D15 (io), 52 I/O40 1A13 (io), 53 I/O41 1A12 (io), 54 I/O42 1A11 (io), 55 I/O43 1A8 (io), 56 I/O44 1A7 (io), 57 I/O45 1A4 (io), 58 I/O46 1A3 (io), 59 I/O47 1A2 (io), 63 I/O48 2A13 (io), 64 I/O49 2A12 (io), 65 I/O50 2A11 (io), 66 I/O51 2A8 (io), 67 I/O52 2A7 (io), 68 I/O53 2A4 (io), 69 I/O54 2A3 (io), 70 I/O55 2A2 (io), 73 I/O56 2B0 (io), 74 I/O57 2B1 (io), 75 I/O58 2B2 (io), 76 I/O59 2B3 (io), 77 I/O60 2B4 (io), 78 I/O61 2B5 (io), 79 I/O62 2B6 (io), 80 I/O63 2B7 (io), 82 I/O64 2B8 (io), 83 I/O65 2B9 (io), 84 I/O66 2B10 (io), 85 I/O67 2B11 (io), 86 I/O68 2B12 (io), 87 I/O69 2B13 (io), 94 I/O70 3B13 (io), 95 I/O71 3B12 (io), 96 I/O72 3B11 (io), 97 I/O73 3B10 (io), 98 I/O74 3B9 (io), 99 I/O75 3B8 (io), 101 I/O76 3B7 (io), 102 I/O77 3B6 (io), 103 I/O78 3B5 (io), 104 I/O79 3B4 (io), 105 I/O80 3B3 (io), 106 I/O81 3B2 (io), 107 I/O82 3B1 (io), 108 I/O83 3B0 (io), 111 I/O84 3A2 (io), 112 I/O85 3A3 (io), 113 I/O86 3A4 (io), 114 I/O87 3A7 (io), 115 I/O88 3A8 (io), 116 I/O89 3A11 (io), 117 I/O90 3A12 (io), 118 I/O91 3A13 (io), 122 I/O92 4A2 (io), 123 I/O93 4A3 (io), 124 I/O94 4A4 (io), 125 I/O95 4A7 (io), 126 I/O96 4A8 (io), 127 I/O97 4A11 (io), 128 I/O98 4A12 (io), 129 I/O99 4A13 (io), 132 I/O100 4D15 (io), 133 I/O101 4D14 (io), 134 I/O102 4D13 (io), 135 I/O103 4D12 (io), 136 I/O104 4D11 (io), 137 I/O105 4D10 (io), 138 I/O106 4D9 (io), 139 I/O107 4D8 (io), 141 I/O108 4D7 (io), 142 I/O109 4D6 (io), 143 I/O110 4D5 (io), 144 I/O111 4D4 (io), 145 I/O112 4D3 (io), 146 I/O113 4D2 (io), 147 I/O114 4D1 (io), 148 I/O115 4D0 (io), 153 I/O116 5D0 (io), 154 I/O117 5D1 (io), 155 I/O118 5D2 (io), 156 I/O119 5D3 (io), 157 I/O120 5D4 (io), 158 I/O121 5D5 (io), 159 I/O122 5D6 (io), 160 I/O123 5D7 (io), 162 I/O124 5D8 (io), 163 I/O125 5D9 (io), 164 I/O126 5D10 (io), 165 I/O127 5D11 (io), 166 I/O128 5D12 (io), 167 I/O129 5D13 (io), 168 I/O130 5D14 (io), 169 I/O131 5D15 (io), 172 I/O132 5A13 (io), 173 I/O133 5A12 (io), 174 I/O134 5A11 (io), 175 I/O135 5A8 (io), 176 I/O136 5A7 (io), 177 I/O137 5A4 (io), 178 I/O138 5A3 (io), 179 I/O139 5A2 (io), 183 I/O140 6A13 (io), 184 I/O141 6A12 (io), 185 I/O142 6A11 (io), 186 I/O143 6A8 (io), 187 I/O144 6A7 (io), 188 I/O145 6A4 (io), 189 I/O146 6A3 (io), 190 I/O147 6A2 (io), 193 I/O148 6B0 (io), 194 I/O149 6B1 (io), 195 I/O150 6B2 (io), 196 I/O151 6B3 (io), 197 I/O152 6B4 (io), 198 I/O153 6B5 (io), 199 I/O154 6B6 (io), 200 I/O155 6B7 (io), 202 I/O156 6B8 (io), 203 I/O157 6B9 (io), 204 I/O158 6B10 (io), 205 I/O159 6B11 (io), 206 I/O160 6B12 (io), 207 I/O161 6B13 (io), 214 I/O162 7B13 (io), 215 I/O163 7B12 (io), 216 I/O164 7B11 (io), 217 I/O165 7B10 (io), 218 I/O166 7B9 (io), 219 I/O167 7B8 (io), 221 I/O168 7B7 (io), 222 I/O169 7B6 (io), 223 I/O170 7B5 (io), 224 I/O171 7B4 (io), 225 I/O172 7B3 (io), 226 I/O173 7B2 (io), 227 I/O174 7B1 (io), 228 I/O175 7B0 (io), 231 I/O176 7A2 (io), 232 I/O177 7A3 (io), 233 I/O178 7A4 (io), 234 I/O179 7A8 (io), 235 I/O180 7A9 (io), 236 I/O181 7A11 (io), 237 I/O182 7A12 (io), 238 I/O183 7A13 (io)
part B pins: 1 TDI (in), 10 VCC (power), 11 GND (power), 20 GND (power), 29 I0/CLK0 (in), 30 VCC (power), 31 GND (power), 32 I1/CLK1 (in), 41 GND (power), 50 GND (power), 51 VCC (power), 60 TCK (in), 61 GND (power), 62 VCC (power), 71 GND (power), 72 VCC (power), 81 GND (power), 88 VCC (power), 89 GND (power), 90 GND (power), 91 GND (power), 92 GND (power), 93 VCC (power), 100 GND (power), 109 VCC (power), 110 GND (power), 119 VCC (power), 120 GND (power), 121 TMS (in), 130 VCC (power), 131 GND (power), 140 GND (power), 149 I2/CLK2 (in), 150 VCC (power), 151 GND (power), 152 I3/CLK3 (in), 161 GND (power), 170 GND (power), 171 VCC (power), 180 TDO (out), 181 GND (power), 182 VCC (power), 191 GND (power), 192 VCC (power), 201 GND (power), 208 VCC (power), 209 GND (power), 210 GND (power), 211 GND (power), 212 GND (power), 213 VCC (power), 220 GND (power), 229 VCC (power), 230 GND (power), 239 VCC (power), 240 GND (power)

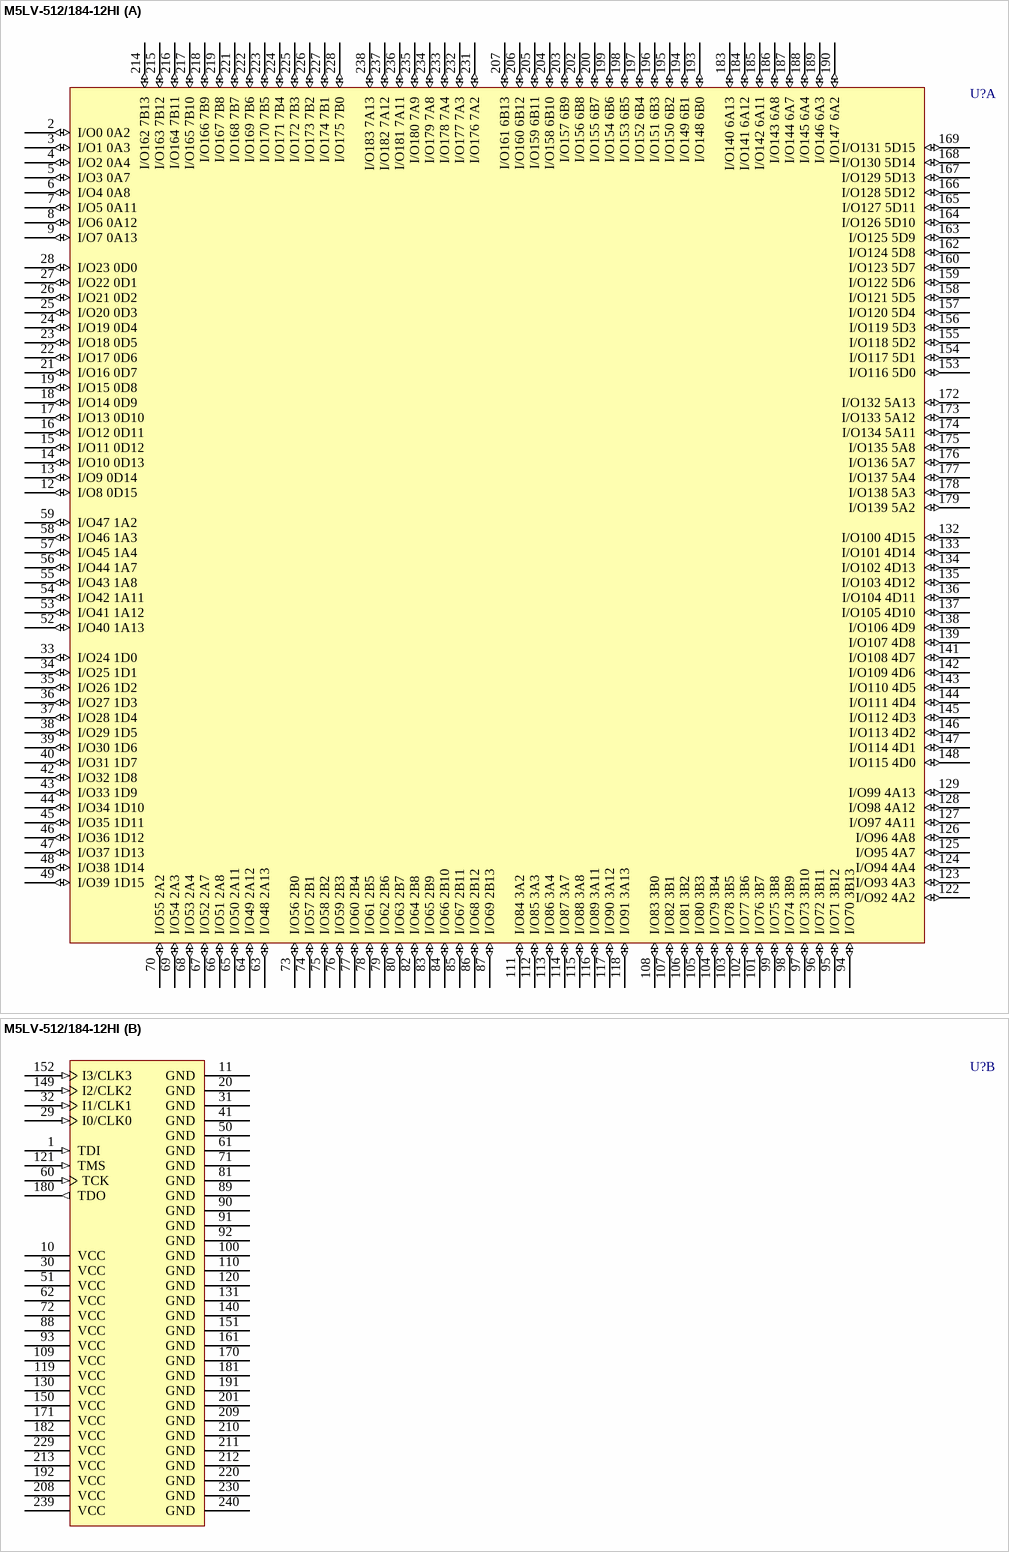
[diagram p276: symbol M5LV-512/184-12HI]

## M5LV-512/184-12HI
designator U?
High-Density and High-I/O Complex PLD
footprint PQFP240_N (Shrink QFP, 240-Leads, Body 32x32mm, Pitch 0.5mm, IPC Medium Density)
footprint PQFP240_L (Shrink QFP, 240-Leads, Body 32x32mm, Pitch 0.5mm, IPC High Density)
footprint PQFP240_M (Shrink QFP, 240-Leads, Body 32x32mm, Pitch 0.5mm, IPC Low Density)
3D model M5LV-PQFP240 (240-Pin Shrink Quad Flat Pack 0.5 mm Pitch)
part A pins: 2 I/O0 0A2 (io), 3 I/O1 0A3 (io), 4 I/O2 0A4 (io), 5 I/O3 0A7 (io), 6 I/O4 0A8 (io), 7 I/O5 0A11 (io), 8 I/O6 0A12 (io), 9 I/O7 0A13 (io), 12 I/O8 0D15 (io), 13 I/O9 0D14 (io), 14 I/O10 0D13 (io), 15 I/O11 0D12 (io), 16 I/O12 0D11 (io), 17 I/O13 0D10 (io), 18 I/O14 0D9 (io), 19 I/O15 0D8 (io), 21 I/O16 0D7 (io), 22 I/O17 0D6 (io), 23 I/O18 0D5 (io), 24 I/O19 0D4 (io), 25 I/O20 0D3 (io), 26 I/O21 0D2 (io), 27 I/O22 0D1 (io), 28 I/O23 0D0 (io), 33 I/O24 1D0 (io), 34 I/O25 1D1 (io), 35 I/O26 1D2 (io), 36 I/O27 1D3 (io), 37 I/O28 1D4 (io), 38 I/O29 1D5 (io), 39 I/O30 1D6 (io), 40 I/O31 1D7 (io), 42 I/O32 1D8 (io), 43 I/O33 1D9 (io), 44 I/O34 1D10 (io), 45 I/O35 1D11 (io), 46 I/O36 1D12 (io), 47 I/O37 1D13 (io), 48 I/O38 1D14 (io), 49 I/O39 1D15 (io), 52 I/O40 1A13 (io), 53 I/O41 1A12 (io), 54 I/O42 1A11 (io), 55 I/O43 1A8 (io), 56 I/O44 1A7 (io), 57 I/O45 1A4 (io), 58 I/O46 1A3 (io), 59 I/O47 1A2 (io), 63 I/O48 2A13 (io), 64 I/O49 2A12 (io), 65 I/O50 2A11 (io), 66 I/O51 2A8 (io), 67 I/O52 2A7 (io), 68 I/O53 2A4 (io), 69 I/O54 2A3 (io), 70 I/O55 2A2 (io), 73 I/O56 2B0 (io), 74 I/O57 2B1 (io), 75 I/O58 2B2 (io), 76 I/O59 2B3 (io), 77 I/O60 2B4 (io), 78 I/O61 2B5 (io), 79 I/O62 2B6 (io), 80 I/O63 2B7 (io), 82 I/O64 2B8 (io), 83 I/O65 2B9 (io), 84 I/O66 2B10 (io), 85 I/O67 2B11 (io), 86 I/O68 2B12 (io), 87 I/O69 2B13 (io), 94 I/O70 3B13 (io), 95 I/O71 3B12 (io), 96 I/O72 3B11 (io), 97 I/O73 3B10 (io), 98 I/O74 3B9 (io), 99 I/O75 3B8 (io), 101 I/O76 3B7 (io), 102 I/O77 3B6 (io), 103 I/O78 3B5 (io), 104 I/O79 3B4 (io), 105 I/O80 3B3 (io), 106 I/O81 3B2 (io), 107 I/O82 3B1 (io), 108 I/O83 3B0 (io), 111 I/O84 3A2 (io), 112 I/O85 3A3 (io), 113 I/O86 3A4 (io), 114 I/O87 3A7 (io), 115 I/O88 3A8 (io), 116 I/O89 3A11 (io), 117 I/O90 3A12 (io), 118 I/O91 3A13 (io), 122 I/O92 4A2 (io), 123 I/O93 4A3 (io), 124 I/O94 4A4 (io), 125 I/O95 4A7 (io), 126 I/O96 4A8 (io), 127 I/O97 4A11 (io), 128 I/O98 4A12 (io), 129 I/O99 4A13 (io), 132 I/O100 4D15 (io), 133 I/O101 4D14 (io), 134 I/O102 4D13 (io), 135 I/O103 4D12 (io), 136 I/O104 4D11 (io), 137 I/O105 4D10 (io), 138 I/O106 4D9 (io), 139 I/O107 4D8 (io), 141 I/O108 4D7 (io), 142 I/O109 4D6 (io), 143 I/O110 4D5 (io), 144 I/O111 4D4 (io), 145 I/O112 4D3 (io), 146 I/O113 4D2 (io), 147 I/O114 4D1 (io), 148 I/O115 4D0 (io), 153 I/O116 5D0 (io), 154 I/O117 5D1 (io), 155 I/O118 5D2 (io), 156 I/O119 5D3 (io), 157 I/O120 5D4 (io), 158 I/O121 5D5 (io), 159 I/O122 5D6 (io), 160 I/O123 5D7 (io), 162 I/O124 5D8 (io), 163 I/O125 5D9 (io), 164 I/O126 5D10 (io), 165 I/O127 5D11 (io), 166 I/O128 5D12 (io), 167 I/O129 5D13 (io), 168 I/O130 5D14 (io), 169 I/O131 5D15 (io), 172 I/O132 5A13 (io), 173 I/O133 5A12 (io), 174 I/O134 5A11 (io), 175 I/O135 5A8 (io), 176 I/O136 5A7 (io), 177 I/O137 5A4 (io), 178 I/O138 5A3 (io), 179 I/O139 5A2 (io), 183 I/O140 6A13 (io), 184 I/O141 6A12 (io), 185 I/O142 6A11 (io), 186 I/O143 6A8 (io), 187 I/O144 6A7 (io), 188 I/O145 6A4 (io), 189 I/O146 6A3 (io), 190 I/O147 6A2 (io), 193 I/O148 6B0 (io), 194 I/O149 6B1 (io), 195 I/O150 6B2 (io), 196 I/O151 6B3 (io), 197 I/O152 6B4 (io), 198 I/O153 6B5 (io), 199 I/O154 6B6 (io), 200 I/O155 6B7 (io), 202 I/O156 6B8 (io), 203 I/O157 6B9 (io), 204 I/O158 6B10 (io), 205 I/O159 6B11 (io), 206 I/O160 6B12 (io), 207 I/O161 6B13 (io), 214 I/O162 7B13 (io), 215 I/O163 7B12 (io), 216 I/O164 7B11 (io), 217 I/O165 7B10 (io), 218 I/O166 7B9 (io), 219 I/O167 7B8 (io), 221 I/O168 7B7 (io), 222 I/O169 7B6 (io), 223 I/O170 7B5 (io), 224 I/O171 7B4 (io), 225 I/O172 7B3 (io), 226 I/O173 7B2 (io), 227 I/O174 7B1 (io), 228 I/O175 7B0 (io), 231 I/O176 7A2 (io), 232 I/O177 7A3 (io), 233 I/O178 7A4 (io), 234 I/O179 7A8 (io), 235 I/O180 7A9 (io), 236 I/O181 7A11 (io), 237 I/O182 7A12 (io), 238 I/O183 7A13 (io)
part B pins: 1 TDI (in), 10 VCC (power), 11 GND (power), 20 GND (power), 29 I0/CLK0 (in), 30 VCC (power), 31 GND (power), 32 I1/CLK1 (in), 41 GND (power), 50 GND (power), 51 VCC (power), 60 TCK (in), 61 GND (power), 62 VCC (power), 71 GND (power), 72 VCC (power), 81 GND (power), 88 VCC (power), 89 GND (power), 90 GND (power), 91 GND (power), 92 GND (power), 93 VCC (power), 100 GND (power), 109 VCC (power), 110 GND (power), 119 VCC (power), 120 GND (power), 121 TMS (in), 130 VCC (power), 131 GND (power), 140 GND (power), 149 I2/CLK2 (in), 150 VCC (power), 151 GND (power), 152 I3/CLK3 (in), 161 GND (power), 170 GND (power), 171 VCC (power), 180 TDO (out), 181 GND (power), 182 VCC (power), 191 GND (power), 192 VCC (power), 201 GND (power), 208 VCC (power), 209 GND (power), 210 GND (power), 211 GND (power), 212 GND (power), 213 VCC (power), 220 GND (power), 229 VCC (power), 230 GND (power), 239 VCC (power), 240 GND (power)

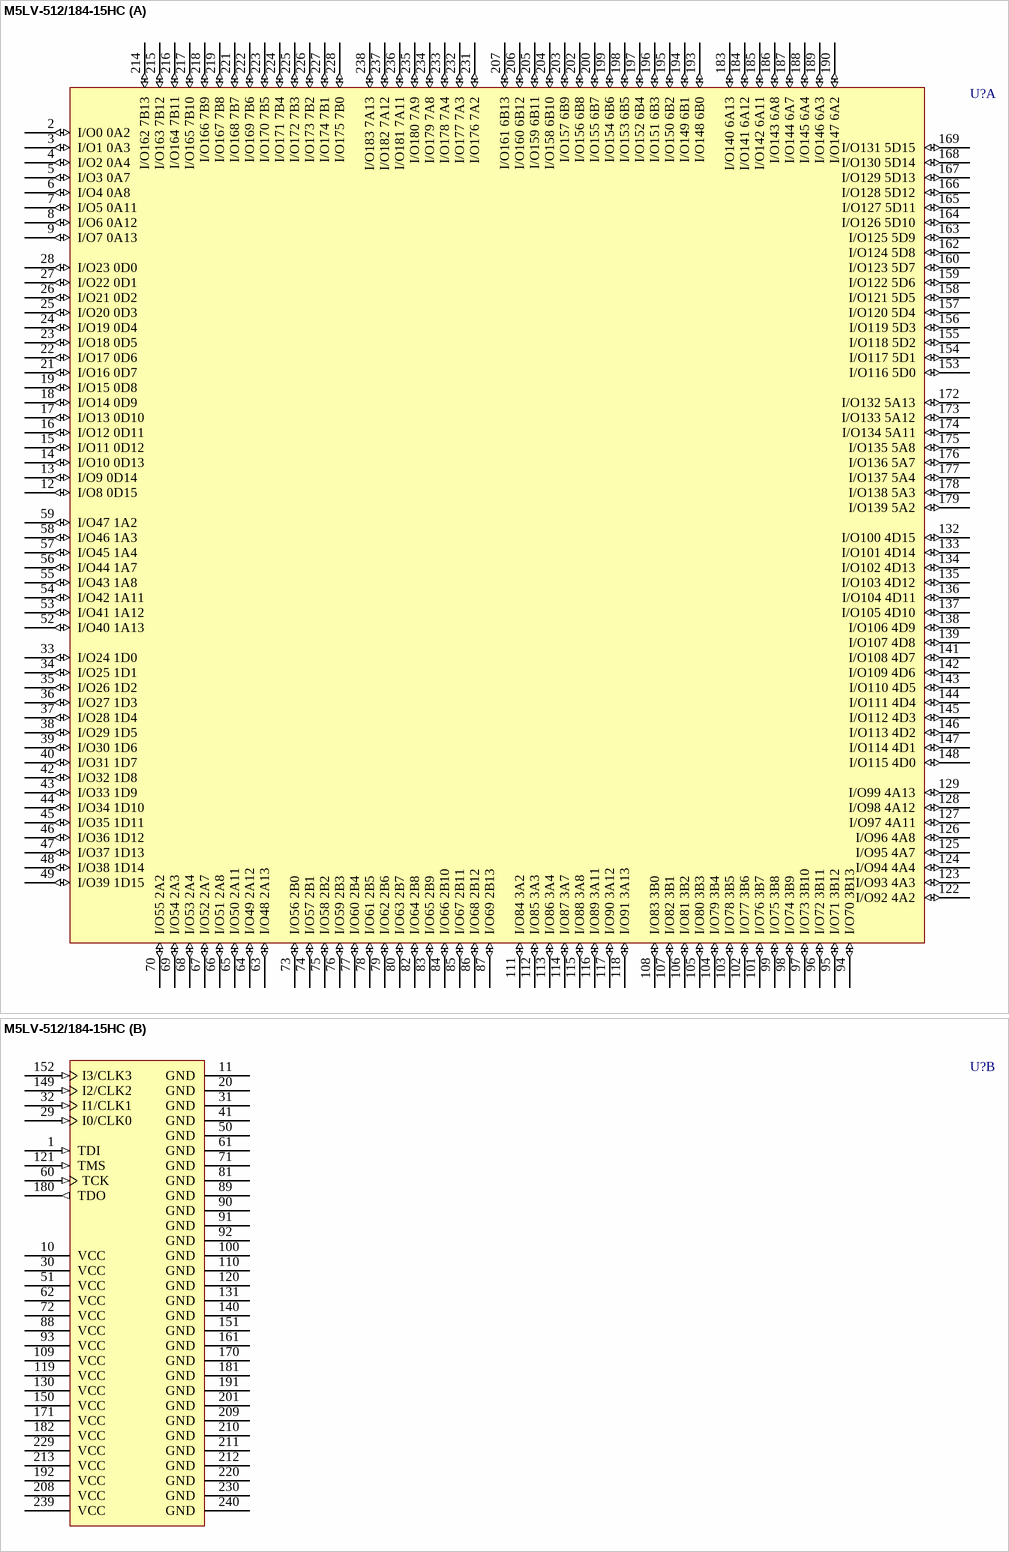
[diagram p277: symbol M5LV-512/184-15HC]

## M5LV-512/184-15HC
designator U?
High-Density and High-I/O Complex PLD
footprint PQFP240_N (Shrink QFP, 240-Leads, Body 32x32mm, Pitch 0.5mm, IPC Medium Density)
footprint PQFP240_L (Shrink QFP, 240-Leads, Body 32x32mm, Pitch 0.5mm, IPC High Density)
footprint PQFP240_M (Shrink QFP, 240-Leads, Body 32x32mm, Pitch 0.5mm, IPC Low Density)
3D model M5LV-PQFP240 (240-Pin Shrink Quad Flat Pack 0.5 mm Pitch)
part A pins: 2 I/O0 0A2 (io), 3 I/O1 0A3 (io), 4 I/O2 0A4 (io), 5 I/O3 0A7 (io), 6 I/O4 0A8 (io), 7 I/O5 0A11 (io), 8 I/O6 0A12 (io), 9 I/O7 0A13 (io), 12 I/O8 0D15 (io), 13 I/O9 0D14 (io), 14 I/O10 0D13 (io), 15 I/O11 0D12 (io), 16 I/O12 0D11 (io), 17 I/O13 0D10 (io), 18 I/O14 0D9 (io), 19 I/O15 0D8 (io), 21 I/O16 0D7 (io), 22 I/O17 0D6 (io), 23 I/O18 0D5 (io), 24 I/O19 0D4 (io), 25 I/O20 0D3 (io), 26 I/O21 0D2 (io), 27 I/O22 0D1 (io), 28 I/O23 0D0 (io), 33 I/O24 1D0 (io), 34 I/O25 1D1 (io), 35 I/O26 1D2 (io), 36 I/O27 1D3 (io), 37 I/O28 1D4 (io), 38 I/O29 1D5 (io), 39 I/O30 1D6 (io), 40 I/O31 1D7 (io), 42 I/O32 1D8 (io), 43 I/O33 1D9 (io), 44 I/O34 1D10 (io), 45 I/O35 1D11 (io), 46 I/O36 1D12 (io), 47 I/O37 1D13 (io), 48 I/O38 1D14 (io), 49 I/O39 1D15 (io), 52 I/O40 1A13 (io), 53 I/O41 1A12 (io), 54 I/O42 1A11 (io), 55 I/O43 1A8 (io), 56 I/O44 1A7 (io), 57 I/O45 1A4 (io), 58 I/O46 1A3 (io), 59 I/O47 1A2 (io), 63 I/O48 2A13 (io), 64 I/O49 2A12 (io), 65 I/O50 2A11 (io), 66 I/O51 2A8 (io), 67 I/O52 2A7 (io), 68 I/O53 2A4 (io), 69 I/O54 2A3 (io), 70 I/O55 2A2 (io), 73 I/O56 2B0 (io), 74 I/O57 2B1 (io), 75 I/O58 2B2 (io), 76 I/O59 2B3 (io), 77 I/O60 2B4 (io), 78 I/O61 2B5 (io), 79 I/O62 2B6 (io), 80 I/O63 2B7 (io), 82 I/O64 2B8 (io), 83 I/O65 2B9 (io), 84 I/O66 2B10 (io), 85 I/O67 2B11 (io), 86 I/O68 2B12 (io), 87 I/O69 2B13 (io), 94 I/O70 3B13 (io), 95 I/O71 3B12 (io), 96 I/O72 3B11 (io), 97 I/O73 3B10 (io), 98 I/O74 3B9 (io), 99 I/O75 3B8 (io), 101 I/O76 3B7 (io), 102 I/O77 3B6 (io), 103 I/O78 3B5 (io), 104 I/O79 3B4 (io), 105 I/O80 3B3 (io), 106 I/O81 3B2 (io), 107 I/O82 3B1 (io), 108 I/O83 3B0 (io), 111 I/O84 3A2 (io), 112 I/O85 3A3 (io), 113 I/O86 3A4 (io), 114 I/O87 3A7 (io), 115 I/O88 3A8 (io), 116 I/O89 3A11 (io), 117 I/O90 3A12 (io), 118 I/O91 3A13 (io), 122 I/O92 4A2 (io), 123 I/O93 4A3 (io), 124 I/O94 4A4 (io), 125 I/O95 4A7 (io), 126 I/O96 4A8 (io), 127 I/O97 4A11 (io), 128 I/O98 4A12 (io), 129 I/O99 4A13 (io), 132 I/O100 4D15 (io), 133 I/O101 4D14 (io), 134 I/O102 4D13 (io), 135 I/O103 4D12 (io), 136 I/O104 4D11 (io), 137 I/O105 4D10 (io), 138 I/O106 4D9 (io), 139 I/O107 4D8 (io), 141 I/O108 4D7 (io), 142 I/O109 4D6 (io), 143 I/O110 4D5 (io), 144 I/O111 4D4 (io), 145 I/O112 4D3 (io), 146 I/O113 4D2 (io), 147 I/O114 4D1 (io), 148 I/O115 4D0 (io), 153 I/O116 5D0 (io), 154 I/O117 5D1 (io), 155 I/O118 5D2 (io), 156 I/O119 5D3 (io), 157 I/O120 5D4 (io), 158 I/O121 5D5 (io), 159 I/O122 5D6 (io), 160 I/O123 5D7 (io), 162 I/O124 5D8 (io), 163 I/O125 5D9 (io), 164 I/O126 5D10 (io), 165 I/O127 5D11 (io), 166 I/O128 5D12 (io), 167 I/O129 5D13 (io), 168 I/O130 5D14 (io), 169 I/O131 5D15 (io), 172 I/O132 5A13 (io), 173 I/O133 5A12 (io), 174 I/O134 5A11 (io), 175 I/O135 5A8 (io), 176 I/O136 5A7 (io), 177 I/O137 5A4 (io), 178 I/O138 5A3 (io), 179 I/O139 5A2 (io), 183 I/O140 6A13 (io), 184 I/O141 6A12 (io), 185 I/O142 6A11 (io), 186 I/O143 6A8 (io), 187 I/O144 6A7 (io), 188 I/O145 6A4 (io), 189 I/O146 6A3 (io), 190 I/O147 6A2 (io), 193 I/O148 6B0 (io), 194 I/O149 6B1 (io), 195 I/O150 6B2 (io), 196 I/O151 6B3 (io), 197 I/O152 6B4 (io), 198 I/O153 6B5 (io), 199 I/O154 6B6 (io), 200 I/O155 6B7 (io), 202 I/O156 6B8 (io), 203 I/O157 6B9 (io), 204 I/O158 6B10 (io), 205 I/O159 6B11 (io), 206 I/O160 6B12 (io), 207 I/O161 6B13 (io), 214 I/O162 7B13 (io), 215 I/O163 7B12 (io), 216 I/O164 7B11 (io), 217 I/O165 7B10 (io), 218 I/O166 7B9 (io), 219 I/O167 7B8 (io), 221 I/O168 7B7 (io), 222 I/O169 7B6 (io), 223 I/O170 7B5 (io), 224 I/O171 7B4 (io), 225 I/O172 7B3 (io), 226 I/O173 7B2 (io), 227 I/O174 7B1 (io), 228 I/O175 7B0 (io), 231 I/O176 7A2 (io), 232 I/O177 7A3 (io), 233 I/O178 7A4 (io), 234 I/O179 7A8 (io), 235 I/O180 7A9 (io), 236 I/O181 7A11 (io), 237 I/O182 7A12 (io), 238 I/O183 7A13 (io)
part B pins: 1 TDI (in), 10 VCC (power), 11 GND (power), 20 GND (power), 29 I0/CLK0 (in), 30 VCC (power), 31 GND (power), 32 I1/CLK1 (in), 41 GND (power), 50 GND (power), 51 VCC (power), 60 TCK (in), 61 GND (power), 62 VCC (power), 71 GND (power), 72 VCC (power), 81 GND (power), 88 VCC (power), 89 GND (power), 90 GND (power), 91 GND (power), 92 GND (power), 93 VCC (power), 100 GND (power), 109 VCC (power), 110 GND (power), 119 VCC (power), 120 GND (power), 121 TMS (in), 130 VCC (power), 131 GND (power), 140 GND (power), 149 I2/CLK2 (in), 150 VCC (power), 151 GND (power), 152 I3/CLK3 (in), 161 GND (power), 170 GND (power), 171 VCC (power), 180 TDO (out), 181 GND (power), 182 VCC (power), 191 GND (power), 192 VCC (power), 201 GND (power), 208 VCC (power), 209 GND (power), 210 GND (power), 211 GND (power), 212 GND (power), 213 VCC (power), 220 GND (power), 229 VCC (power), 230 GND (power), 239 VCC (power), 240 GND (power)

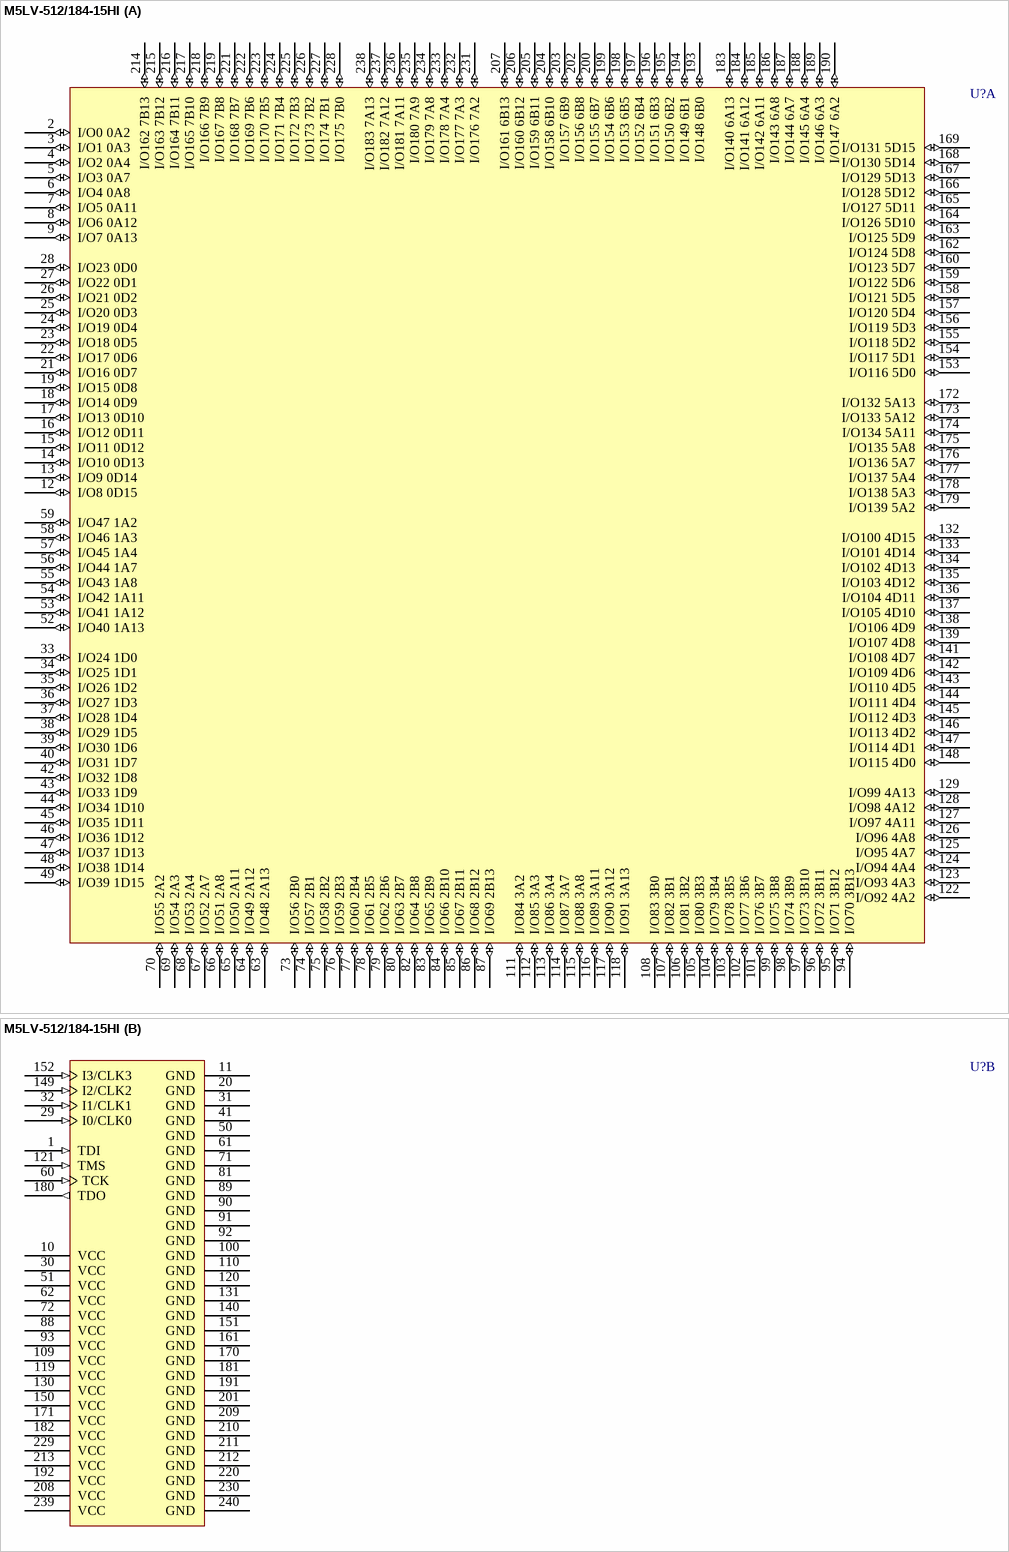
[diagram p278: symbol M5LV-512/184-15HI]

## M5LV-512/184-15HI
designator U?
High-Density and High-I/O Complex PLD
footprint PQFP240_N (Shrink QFP, 240-Leads, Body 32x32mm, Pitch 0.5mm, IPC Medium Density)
footprint PQFP240_L (Shrink QFP, 240-Leads, Body 32x32mm, Pitch 0.5mm, IPC High Density)
footprint PQFP240_M (Shrink QFP, 240-Leads, Body 32x32mm, Pitch 0.5mm, IPC Low Density)
3D model M5LV-PQFP240 (240-Pin Shrink Quad Flat Pack 0.5 mm Pitch)
part A pins: 2 I/O0 0A2 (io), 3 I/O1 0A3 (io), 4 I/O2 0A4 (io), 5 I/O3 0A7 (io), 6 I/O4 0A8 (io), 7 I/O5 0A11 (io), 8 I/O6 0A12 (io), 9 I/O7 0A13 (io), 12 I/O8 0D15 (io), 13 I/O9 0D14 (io), 14 I/O10 0D13 (io), 15 I/O11 0D12 (io), 16 I/O12 0D11 (io), 17 I/O13 0D10 (io), 18 I/O14 0D9 (io), 19 I/O15 0D8 (io), 21 I/O16 0D7 (io), 22 I/O17 0D6 (io), 23 I/O18 0D5 (io), 24 I/O19 0D4 (io), 25 I/O20 0D3 (io), 26 I/O21 0D2 (io), 27 I/O22 0D1 (io), 28 I/O23 0D0 (io), 33 I/O24 1D0 (io), 34 I/O25 1D1 (io), 35 I/O26 1D2 (io), 36 I/O27 1D3 (io), 37 I/O28 1D4 (io), 38 I/O29 1D5 (io), 39 I/O30 1D6 (io), 40 I/O31 1D7 (io), 42 I/O32 1D8 (io), 43 I/O33 1D9 (io), 44 I/O34 1D10 (io), 45 I/O35 1D11 (io), 46 I/O36 1D12 (io), 47 I/O37 1D13 (io), 48 I/O38 1D14 (io), 49 I/O39 1D15 (io), 52 I/O40 1A13 (io), 53 I/O41 1A12 (io), 54 I/O42 1A11 (io), 55 I/O43 1A8 (io), 56 I/O44 1A7 (io), 57 I/O45 1A4 (io), 58 I/O46 1A3 (io), 59 I/O47 1A2 (io), 63 I/O48 2A13 (io), 64 I/O49 2A12 (io), 65 I/O50 2A11 (io), 66 I/O51 2A8 (io), 67 I/O52 2A7 (io), 68 I/O53 2A4 (io), 69 I/O54 2A3 (io), 70 I/O55 2A2 (io), 73 I/O56 2B0 (io), 74 I/O57 2B1 (io), 75 I/O58 2B2 (io), 76 I/O59 2B3 (io), 77 I/O60 2B4 (io), 78 I/O61 2B5 (io), 79 I/O62 2B6 (io), 80 I/O63 2B7 (io), 82 I/O64 2B8 (io), 83 I/O65 2B9 (io), 84 I/O66 2B10 (io), 85 I/O67 2B11 (io), 86 I/O68 2B12 (io), 87 I/O69 2B13 (io), 94 I/O70 3B13 (io), 95 I/O71 3B12 (io), 96 I/O72 3B11 (io), 97 I/O73 3B10 (io), 98 I/O74 3B9 (io), 99 I/O75 3B8 (io), 101 I/O76 3B7 (io), 102 I/O77 3B6 (io), 103 I/O78 3B5 (io), 104 I/O79 3B4 (io), 105 I/O80 3B3 (io), 106 I/O81 3B2 (io), 107 I/O82 3B1 (io), 108 I/O83 3B0 (io), 111 I/O84 3A2 (io), 112 I/O85 3A3 (io), 113 I/O86 3A4 (io), 114 I/O87 3A7 (io), 115 I/O88 3A8 (io), 116 I/O89 3A11 (io), 117 I/O90 3A12 (io), 118 I/O91 3A13 (io), 122 I/O92 4A2 (io), 123 I/O93 4A3 (io), 124 I/O94 4A4 (io), 125 I/O95 4A7 (io), 126 I/O96 4A8 (io), 127 I/O97 4A11 (io), 128 I/O98 4A12 (io), 129 I/O99 4A13 (io), 132 I/O100 4D15 (io), 133 I/O101 4D14 (io), 134 I/O102 4D13 (io), 135 I/O103 4D12 (io), 136 I/O104 4D11 (io), 137 I/O105 4D10 (io), 138 I/O106 4D9 (io), 139 I/O107 4D8 (io), 141 I/O108 4D7 (io), 142 I/O109 4D6 (io), 143 I/O110 4D5 (io), 144 I/O111 4D4 (io), 145 I/O112 4D3 (io), 146 I/O113 4D2 (io), 147 I/O114 4D1 (io), 148 I/O115 4D0 (io), 153 I/O116 5D0 (io), 154 I/O117 5D1 (io), 155 I/O118 5D2 (io), 156 I/O119 5D3 (io), 157 I/O120 5D4 (io), 158 I/O121 5D5 (io), 159 I/O122 5D6 (io), 160 I/O123 5D7 (io), 162 I/O124 5D8 (io), 163 I/O125 5D9 (io), 164 I/O126 5D10 (io), 165 I/O127 5D11 (io), 166 I/O128 5D12 (io), 167 I/O129 5D13 (io), 168 I/O130 5D14 (io), 169 I/O131 5D15 (io), 172 I/O132 5A13 (io), 173 I/O133 5A12 (io), 174 I/O134 5A11 (io), 175 I/O135 5A8 (io), 176 I/O136 5A7 (io), 177 I/O137 5A4 (io), 178 I/O138 5A3 (io), 179 I/O139 5A2 (io), 183 I/O140 6A13 (io), 184 I/O141 6A12 (io), 185 I/O142 6A11 (io), 186 I/O143 6A8 (io), 187 I/O144 6A7 (io), 188 I/O145 6A4 (io), 189 I/O146 6A3 (io), 190 I/O147 6A2 (io), 193 I/O148 6B0 (io), 194 I/O149 6B1 (io), 195 I/O150 6B2 (io), 196 I/O151 6B3 (io), 197 I/O152 6B4 (io), 198 I/O153 6B5 (io), 199 I/O154 6B6 (io), 200 I/O155 6B7 (io), 202 I/O156 6B8 (io), 203 I/O157 6B9 (io), 204 I/O158 6B10 (io), 205 I/O159 6B11 (io), 206 I/O160 6B12 (io), 207 I/O161 6B13 (io), 214 I/O162 7B13 (io), 215 I/O163 7B12 (io), 216 I/O164 7B11 (io), 217 I/O165 7B10 (io), 218 I/O166 7B9 (io), 219 I/O167 7B8 (io), 221 I/O168 7B7 (io), 222 I/O169 7B6 (io), 223 I/O170 7B5 (io), 224 I/O171 7B4 (io), 225 I/O172 7B3 (io), 226 I/O173 7B2 (io), 227 I/O174 7B1 (io), 228 I/O175 7B0 (io), 231 I/O176 7A2 (io), 232 I/O177 7A3 (io), 233 I/O178 7A4 (io), 234 I/O179 7A8 (io), 235 I/O180 7A9 (io), 236 I/O181 7A11 (io), 237 I/O182 7A12 (io), 238 I/O183 7A13 (io)
part B pins: 1 TDI (in), 10 VCC (power), 11 GND (power), 20 GND (power), 29 I0/CLK0 (in), 30 VCC (power), 31 GND (power), 32 I1/CLK1 (in), 41 GND (power), 50 GND (power), 51 VCC (power), 60 TCK (in), 61 GND (power), 62 VCC (power), 71 GND (power), 72 VCC (power), 81 GND (power), 88 VCC (power), 89 GND (power), 90 GND (power), 91 GND (power), 92 GND (power), 93 VCC (power), 100 GND (power), 109 VCC (power), 110 GND (power), 119 VCC (power), 120 GND (power), 121 TMS (in), 130 VCC (power), 131 GND (power), 140 GND (power), 149 I2/CLK2 (in), 150 VCC (power), 151 GND (power), 152 I3/CLK3 (in), 161 GND (power), 170 GND (power), 171 VCC (power), 180 TDO (out), 181 GND (power), 182 VCC (power), 191 GND (power), 192 VCC (power), 201 GND (power), 208 VCC (power), 209 GND (power), 210 GND (power), 211 GND (power), 212 GND (power), 213 VCC (power), 220 GND (power), 229 VCC (power), 230 GND (power), 239 VCC (power), 240 GND (power)

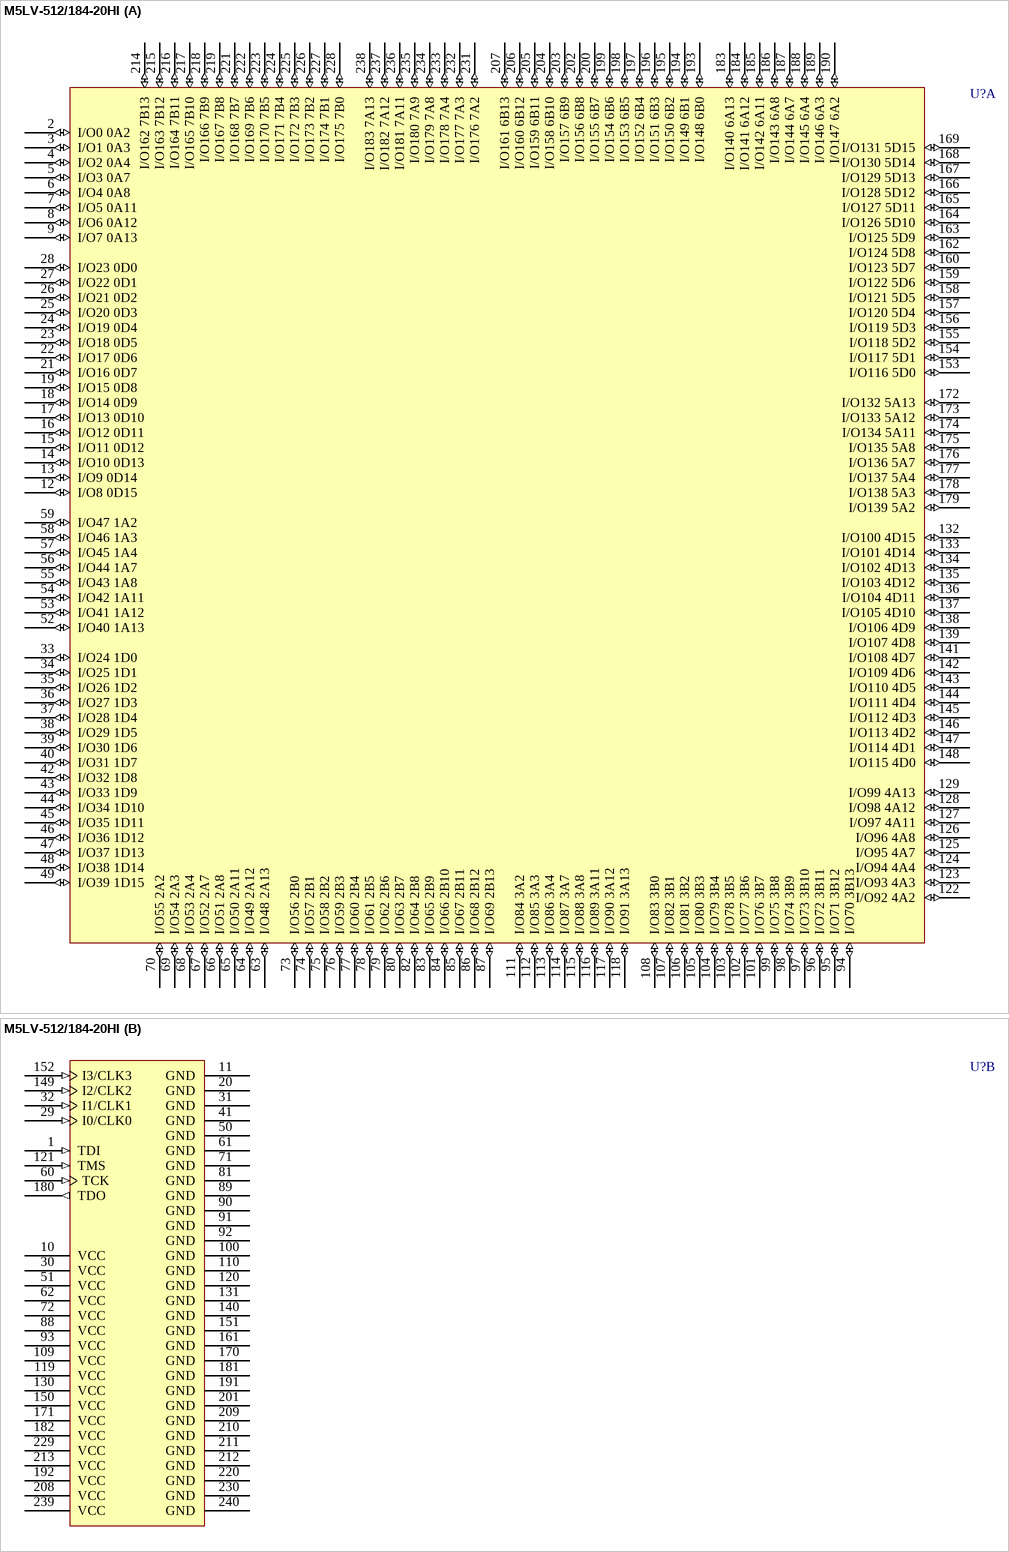
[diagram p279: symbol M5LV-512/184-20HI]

## M5LV-512/184-20HI
designator U?
High-Density and High-I/O Complex PLD
footprint PQFP240_N (Shrink QFP, 240-Leads, Body 32x32mm, Pitch 0.5mm, IPC Medium Density)
footprint PQFP240_L (Shrink QFP, 240-Leads, Body 32x32mm, Pitch 0.5mm, IPC High Density)
footprint PQFP240_M (Shrink QFP, 240-Leads, Body 32x32mm, Pitch 0.5mm, IPC Low Density)
3D model M5LV-PQFP240 (240-Pin Shrink Quad Flat Pack 0.5 mm Pitch)
part A pins: 2 I/O0 0A2 (io), 3 I/O1 0A3 (io), 4 I/O2 0A4 (io), 5 I/O3 0A7 (io), 6 I/O4 0A8 (io), 7 I/O5 0A11 (io), 8 I/O6 0A12 (io), 9 I/O7 0A13 (io), 12 I/O8 0D15 (io), 13 I/O9 0D14 (io), 14 I/O10 0D13 (io), 15 I/O11 0D12 (io), 16 I/O12 0D11 (io), 17 I/O13 0D10 (io), 18 I/O14 0D9 (io), 19 I/O15 0D8 (io), 21 I/O16 0D7 (io), 22 I/O17 0D6 (io), 23 I/O18 0D5 (io), 24 I/O19 0D4 (io), 25 I/O20 0D3 (io), 26 I/O21 0D2 (io), 27 I/O22 0D1 (io), 28 I/O23 0D0 (io), 33 I/O24 1D0 (io), 34 I/O25 1D1 (io), 35 I/O26 1D2 (io), 36 I/O27 1D3 (io), 37 I/O28 1D4 (io), 38 I/O29 1D5 (io), 39 I/O30 1D6 (io), 40 I/O31 1D7 (io), 42 I/O32 1D8 (io), 43 I/O33 1D9 (io), 44 I/O34 1D10 (io), 45 I/O35 1D11 (io), 46 I/O36 1D12 (io), 47 I/O37 1D13 (io), 48 I/O38 1D14 (io), 49 I/O39 1D15 (io), 52 I/O40 1A13 (io), 53 I/O41 1A12 (io), 54 I/O42 1A11 (io), 55 I/O43 1A8 (io), 56 I/O44 1A7 (io), 57 I/O45 1A4 (io), 58 I/O46 1A3 (io), 59 I/O47 1A2 (io), 63 I/O48 2A13 (io), 64 I/O49 2A12 (io), 65 I/O50 2A11 (io), 66 I/O51 2A8 (io), 67 I/O52 2A7 (io), 68 I/O53 2A4 (io), 69 I/O54 2A3 (io), 70 I/O55 2A2 (io), 73 I/O56 2B0 (io), 74 I/O57 2B1 (io), 75 I/O58 2B2 (io), 76 I/O59 2B3 (io), 77 I/O60 2B4 (io), 78 I/O61 2B5 (io), 79 I/O62 2B6 (io), 80 I/O63 2B7 (io), 82 I/O64 2B8 (io), 83 I/O65 2B9 (io), 84 I/O66 2B10 (io), 85 I/O67 2B11 (io), 86 I/O68 2B12 (io), 87 I/O69 2B13 (io), 94 I/O70 3B13 (io), 95 I/O71 3B12 (io), 96 I/O72 3B11 (io), 97 I/O73 3B10 (io), 98 I/O74 3B9 (io), 99 I/O75 3B8 (io), 101 I/O76 3B7 (io), 102 I/O77 3B6 (io), 103 I/O78 3B5 (io), 104 I/O79 3B4 (io), 105 I/O80 3B3 (io), 106 I/O81 3B2 (io), 107 I/O82 3B1 (io), 108 I/O83 3B0 (io), 111 I/O84 3A2 (io), 112 I/O85 3A3 (io), 113 I/O86 3A4 (io), 114 I/O87 3A7 (io), 115 I/O88 3A8 (io), 116 I/O89 3A11 (io), 117 I/O90 3A12 (io), 118 I/O91 3A13 (io), 122 I/O92 4A2 (io), 123 I/O93 4A3 (io), 124 I/O94 4A4 (io), 125 I/O95 4A7 (io), 126 I/O96 4A8 (io), 127 I/O97 4A11 (io), 128 I/O98 4A12 (io), 129 I/O99 4A13 (io), 132 I/O100 4D15 (io), 133 I/O101 4D14 (io), 134 I/O102 4D13 (io), 135 I/O103 4D12 (io), 136 I/O104 4D11 (io), 137 I/O105 4D10 (io), 138 I/O106 4D9 (io), 139 I/O107 4D8 (io), 141 I/O108 4D7 (io), 142 I/O109 4D6 (io), 143 I/O110 4D5 (io), 144 I/O111 4D4 (io), 145 I/O112 4D3 (io), 146 I/O113 4D2 (io), 147 I/O114 4D1 (io), 148 I/O115 4D0 (io), 153 I/O116 5D0 (io), 154 I/O117 5D1 (io), 155 I/O118 5D2 (io), 156 I/O119 5D3 (io), 157 I/O120 5D4 (io), 158 I/O121 5D5 (io), 159 I/O122 5D6 (io), 160 I/O123 5D7 (io), 162 I/O124 5D8 (io), 163 I/O125 5D9 (io), 164 I/O126 5D10 (io), 165 I/O127 5D11 (io), 166 I/O128 5D12 (io), 167 I/O129 5D13 (io), 168 I/O130 5D14 (io), 169 I/O131 5D15 (io), 172 I/O132 5A13 (io), 173 I/O133 5A12 (io), 174 I/O134 5A11 (io), 175 I/O135 5A8 (io), 176 I/O136 5A7 (io), 177 I/O137 5A4 (io), 178 I/O138 5A3 (io), 179 I/O139 5A2 (io), 183 I/O140 6A13 (io), 184 I/O141 6A12 (io), 185 I/O142 6A11 (io), 186 I/O143 6A8 (io), 187 I/O144 6A7 (io), 188 I/O145 6A4 (io), 189 I/O146 6A3 (io), 190 I/O147 6A2 (io), 193 I/O148 6B0 (io), 194 I/O149 6B1 (io), 195 I/O150 6B2 (io), 196 I/O151 6B3 (io), 197 I/O152 6B4 (io), 198 I/O153 6B5 (io), 199 I/O154 6B6 (io), 200 I/O155 6B7 (io), 202 I/O156 6B8 (io), 203 I/O157 6B9 (io), 204 I/O158 6B10 (io), 205 I/O159 6B11 (io), 206 I/O160 6B12 (io), 207 I/O161 6B13 (io), 214 I/O162 7B13 (io), 215 I/O163 7B12 (io), 216 I/O164 7B11 (io), 217 I/O165 7B10 (io), 218 I/O166 7B9 (io), 219 I/O167 7B8 (io), 221 I/O168 7B7 (io), 222 I/O169 7B6 (io), 223 I/O170 7B5 (io), 224 I/O171 7B4 (io), 225 I/O172 7B3 (io), 226 I/O173 7B2 (io), 227 I/O174 7B1 (io), 228 I/O175 7B0 (io), 231 I/O176 7A2 (io), 232 I/O177 7A3 (io), 233 I/O178 7A4 (io), 234 I/O179 7A8 (io), 235 I/O180 7A9 (io), 236 I/O181 7A11 (io), 237 I/O182 7A12 (io), 238 I/O183 7A13 (io)
part B pins: 1 TDI (in), 10 VCC (power), 11 GND (power), 20 GND (power), 29 I0/CLK0 (in), 30 VCC (power), 31 GND (power), 32 I1/CLK1 (in), 41 GND (power), 50 GND (power), 51 VCC (power), 60 TCK (in), 61 GND (power), 62 VCC (power), 71 GND (power), 72 VCC (power), 81 GND (power), 88 VCC (power), 89 GND (power), 90 GND (power), 91 GND (power), 92 GND (power), 93 VCC (power), 100 GND (power), 109 VCC (power), 110 GND (power), 119 VCC (power), 120 GND (power), 121 TMS (in), 130 VCC (power), 131 GND (power), 140 GND (power), 149 I2/CLK2 (in), 150 VCC (power), 151 GND (power), 152 I3/CLK3 (in), 161 GND (power), 170 GND (power), 171 VCC (power), 180 TDO (out), 181 GND (power), 182 VCC (power), 191 GND (power), 192 VCC (power), 201 GND (power), 208 VCC (power), 209 GND (power), 210 GND (power), 211 GND (power), 212 GND (power), 213 VCC (power), 220 GND (power), 229 VCC (power), 230 GND (power), 239 VCC (power), 240 GND (power)

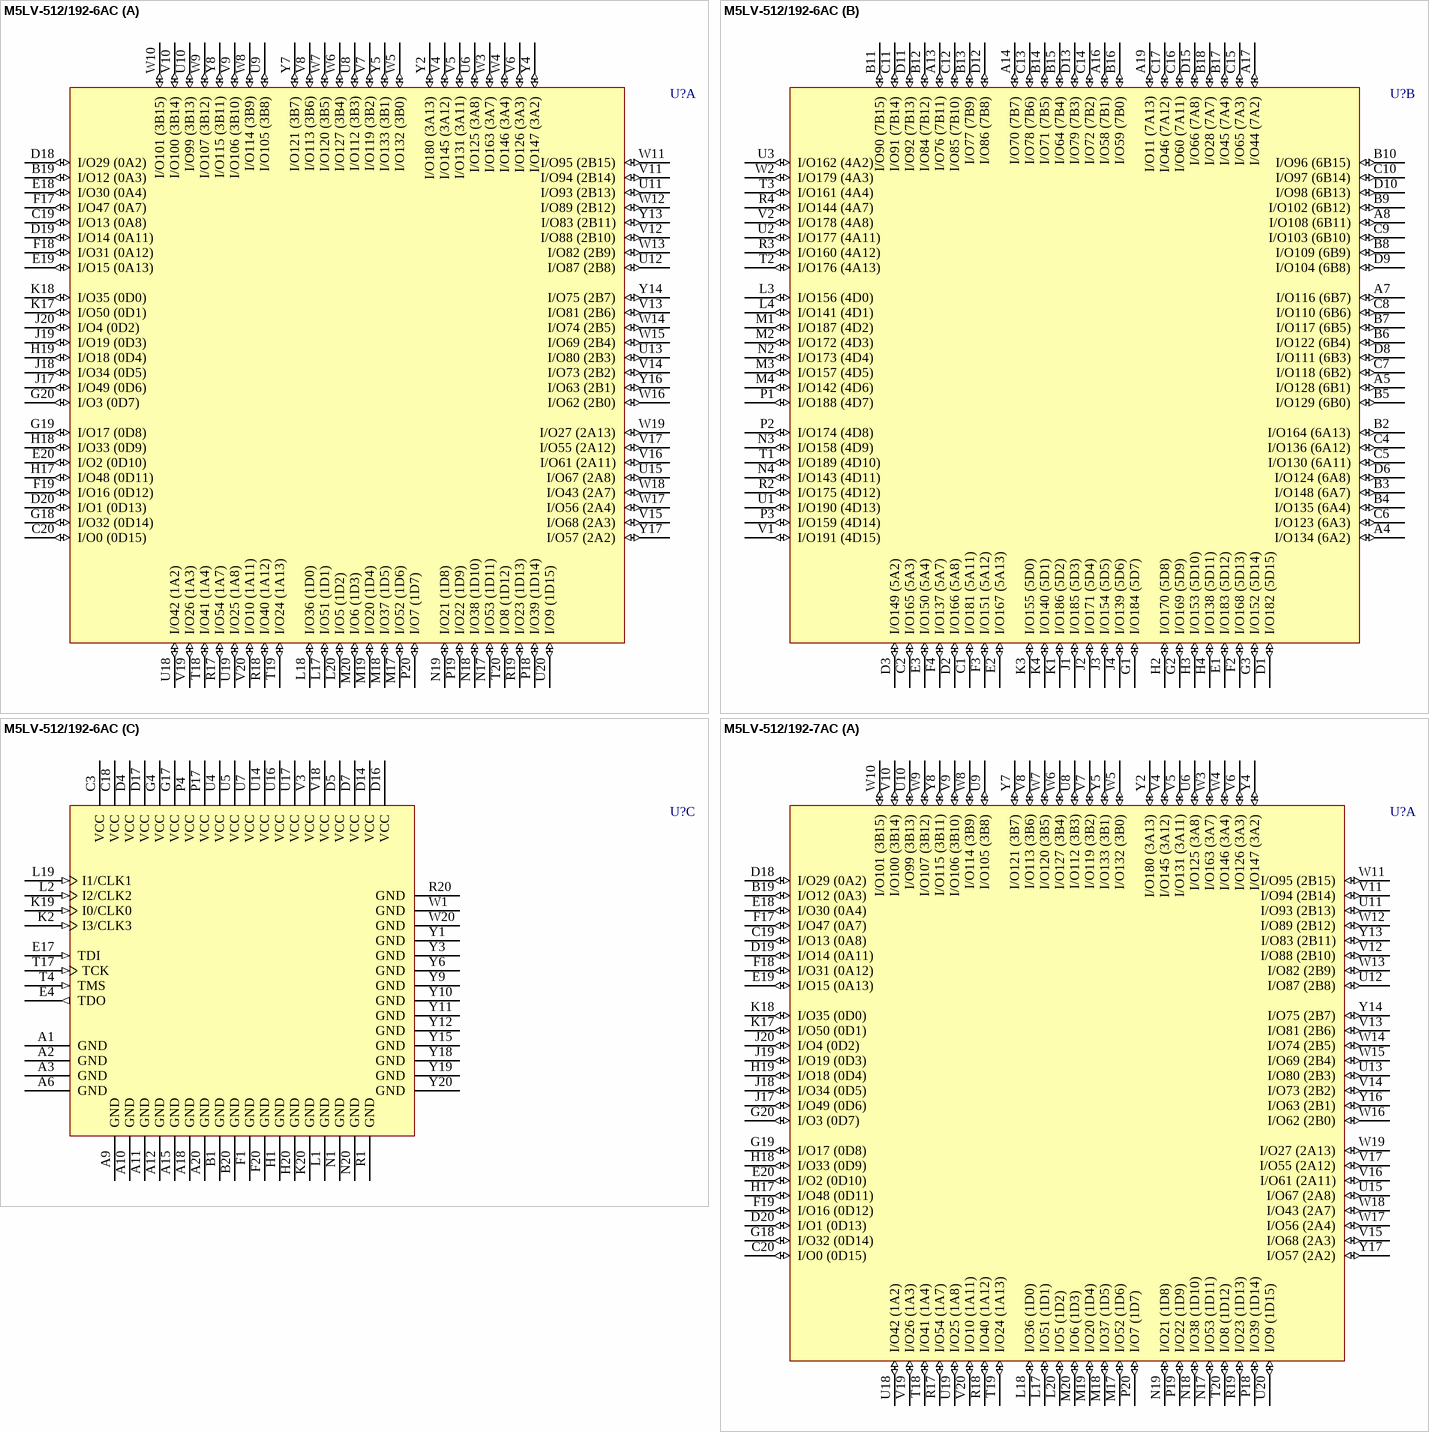
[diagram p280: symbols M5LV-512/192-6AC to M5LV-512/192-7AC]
